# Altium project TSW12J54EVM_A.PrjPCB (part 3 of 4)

## Sheet TSW12J54EVM_A_5_Power.SchDoc
size 431 x 279 mm; Date: Not shown in title block; ApprovedBy: Not shown in title block; CheckedBy: Not shown in title block; Author: Not shown in title block; CompanyName: Not shown in title block; Engineer: Not shown in title block; Organization: Not shown in title block; Address1: Not shown in title block; Address2: Not shown in title block; Address3: Not shown in title block; Address4: Not shown in title block; DocumentNumber: 5; Revision: Use project parameter SCH_Rev; SheetNumber: 5; SheetTotal: 8; PageSetup: Record=PageOptions¦CenterHorizontal=True¦CenterVertical=True¦PrintScale=0.64¦XCorrection=1.00¦YCorrection=1.00¦PrintKind=0¦BorderSize=5000000¦LeftOffset=0¦BottomOffset=0¦Orientation=2¦PaperLength=1000¦PaperWidth=1000¦Scale=100¦PaperSource=15¦PrintQuality=600¦MediaType=1¦DitherType=10¦PaperKind=11x17¦PrintScaleMode=1
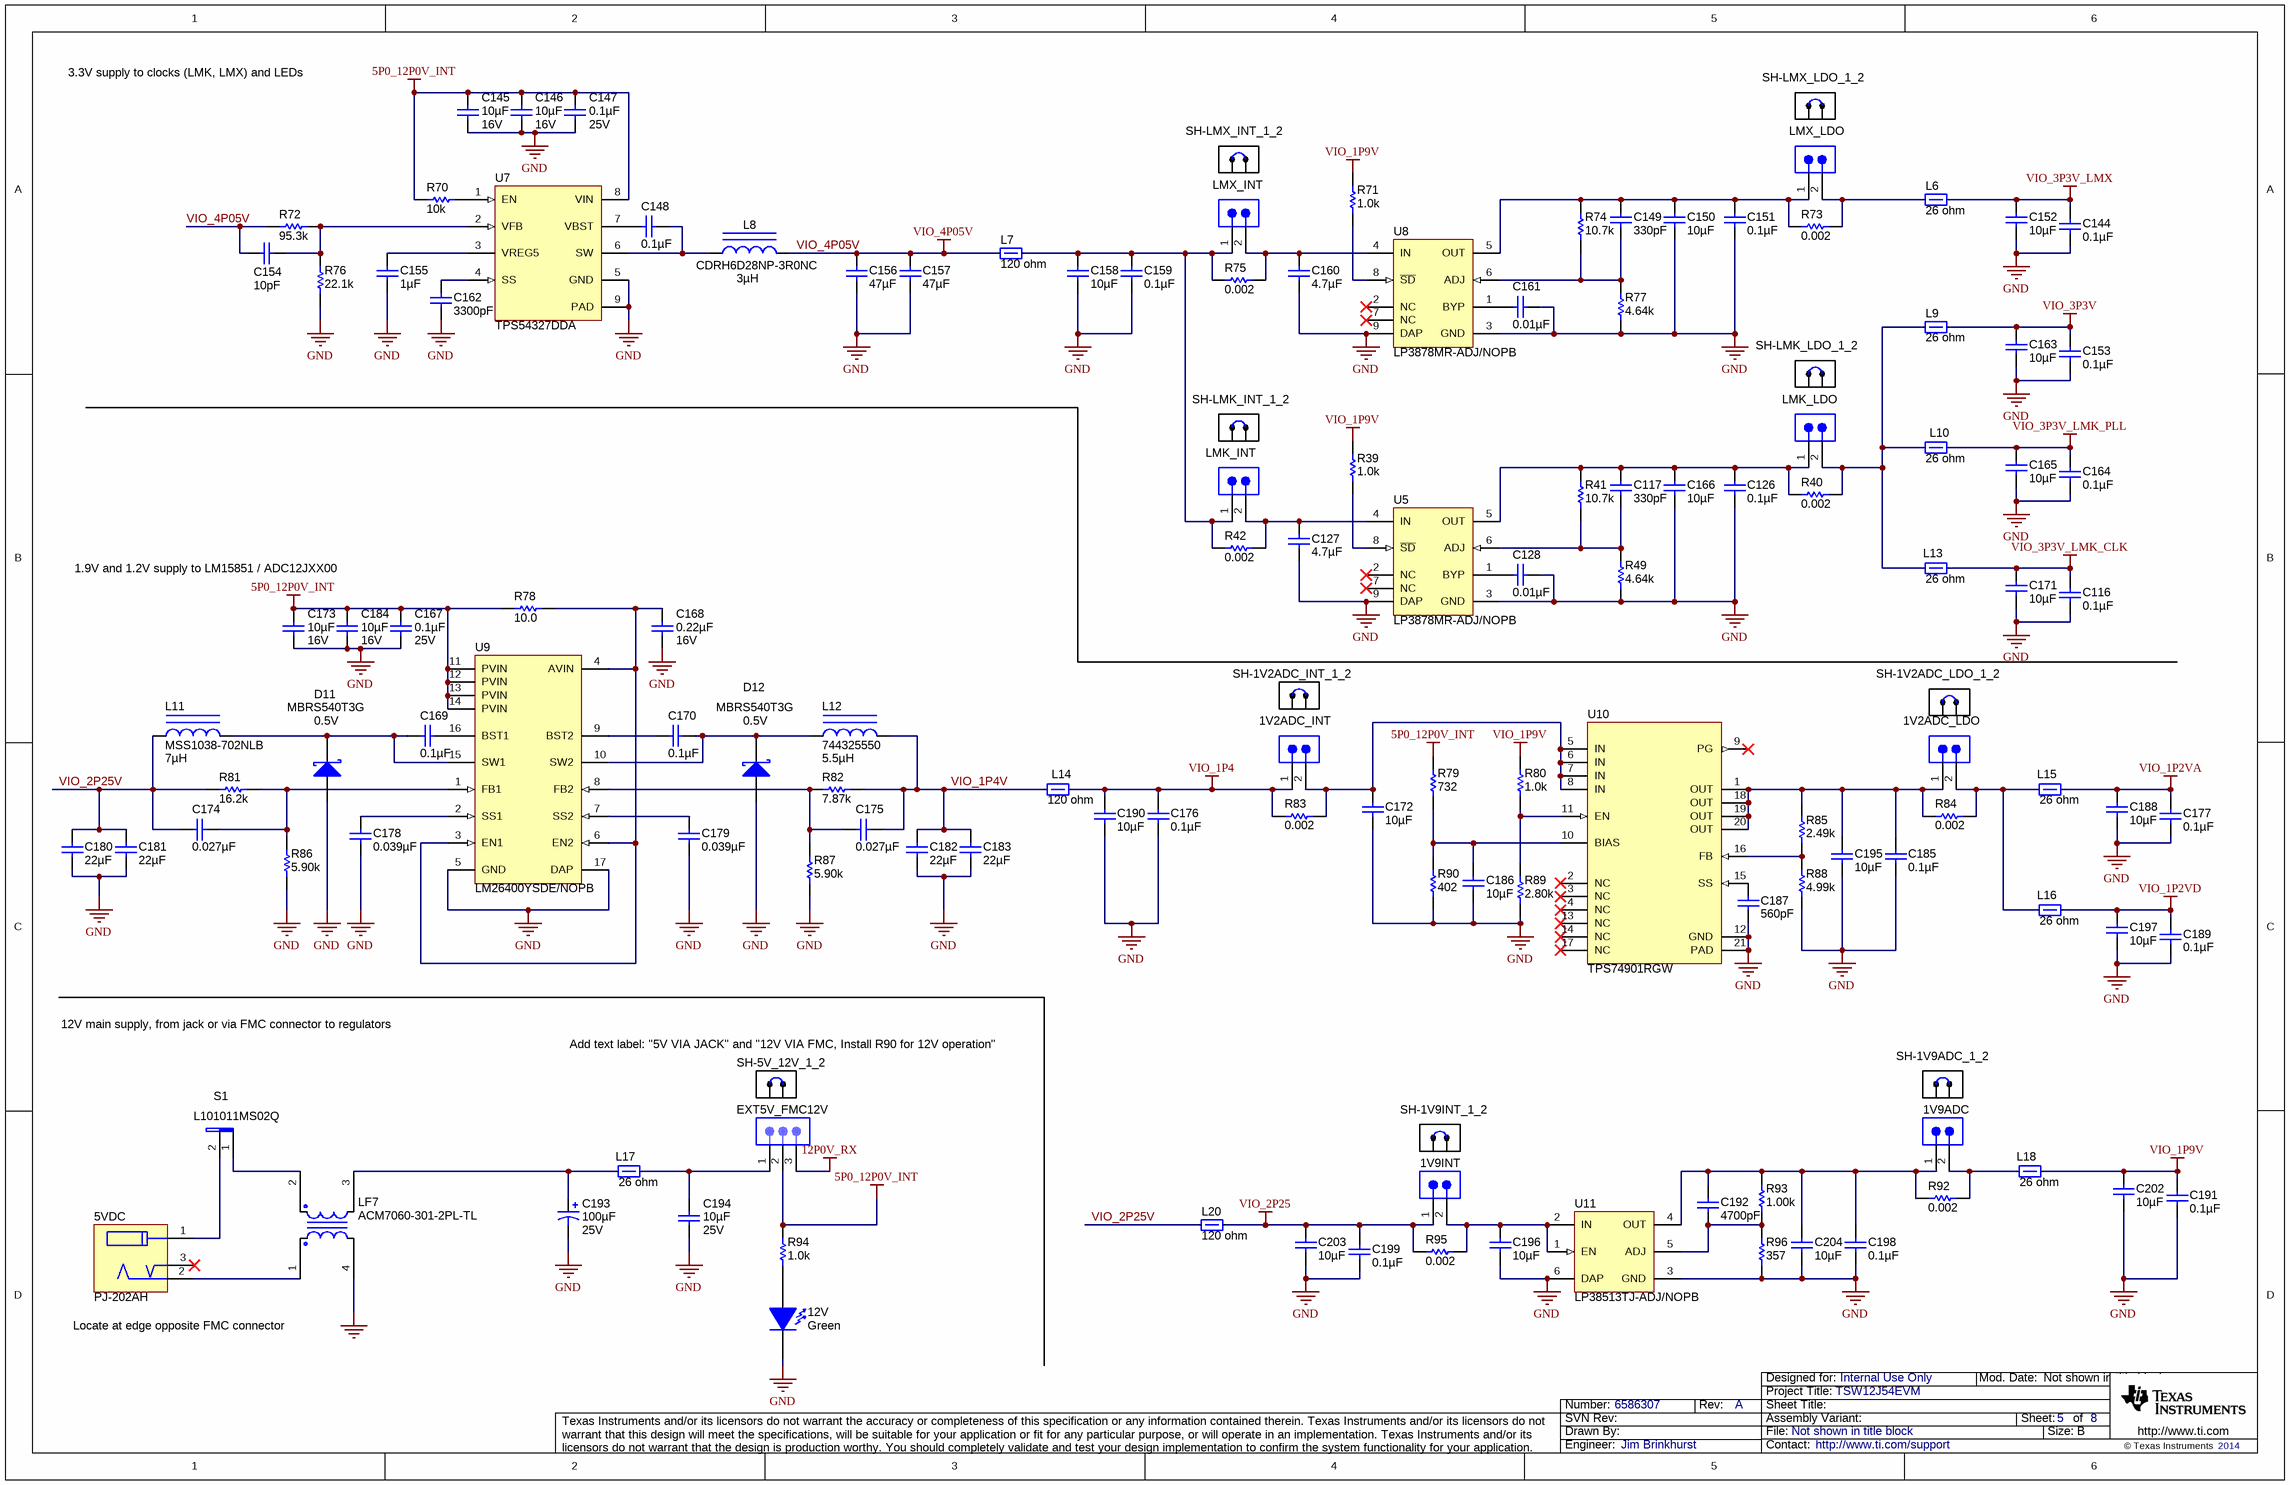
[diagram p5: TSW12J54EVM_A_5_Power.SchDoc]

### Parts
1V2ADC_INT  TSW-102-07-G-S  [TSW-102-07-G-S]  (value not drawn)
1V2ADC_LDO  TSW-102-07-G-S  [TSW-102-07-G-S]  (value not drawn)
1V9ADC  TSW-102-07-G-S  [TSW-102-07-G-S]  (value not drawn)
1V9INT  TSW-102-07-G-S  [TSW-102-07-G-S]  (value not drawn)
5VDC  PJ-202AH  [CONN_CUI-PJ-202AH]
12V  value Green  [LED_LTST-C190]  (hidden comment: LTST-C190GKT)
C116  ValueDisplayed: 0.1µF  [0603L]  (hidden comment: 06033C104JAT2A)
C117  ValueDisplayed: 330pF  [0603L]  (hidden comment: 06035A331JAT2A)
C126  ValueDisplayed: 0.1µF  [0603L]  (hidden comment: 06033C104JAT2A)
C127  ValueDisplayed: 4.7µF  [0603L]  (hidden comment: C0603C475K8PACTU)
C128  ValueDisplayed: 0.01µF  [0603L]  (hidden comment: 06031C103MAT2A)
C144  ValueDisplayed: 0.1µF  [0603L]  (hidden comment: 06033C104JAT2A)
C145  ValueDisplayed: 10µF  Value2: 16V  [0805L]  (hidden comment: EMK212BJ106KG-T)
C146  ValueDisplayed: 10µF  Value2: 16V  [0805L]  (hidden comment: EMK212BJ106KG-T)
C147  ValueDisplayed: 0.1µF  Value2: 25V  [0603L]  (hidden comment: 06033C104JAT2A)
C148  ValueDisplayed: 0.1µF  [0603L]  (hidden comment: 06033C104JAT2A)
C149  ValueDisplayed: 330pF  [0603L]  (hidden comment: 06035A331JAT2A)
C150  ValueDisplayed: 10µF  [0603L]  (hidden comment: C1608X5R1A106M)
C151  ValueDisplayed: 0.1µF  [0603L]  (hidden comment: 06033C104JAT2A)
C152  ValueDisplayed: 10µF  [0603L]  (hidden comment: C1608X5R1A106M)
C153  ValueDisplayed: 0.1µF  [0603L]  (hidden comment: 06033C104JAT2A)
C154  ValueDisplayed: 10pF  [0603L]  (hidden comment: 06035A100JAT2A)
C155  ValueDisplayed: 1µF  [0603L]  (hidden comment: C1608X5R1C105K)
C156  ValueDisplayed: 47µF  [1206L]  (hidden comment: GRM31CR60J476ME19L)
C157  ValueDisplayed: 47µF  [1206L]  (hidden comment: GRM31CR60J476ME19L)
C158  ValueDisplayed: 10µF  [0603L]  (hidden comment: C1608X5R1A106M)
C159  ValueDisplayed: 0.1µF  [0603L]  (hidden comment: 06033C104JAT2A)
C160  ValueDisplayed: 4.7µF  [0603L]  (hidden comment: C0603C475K8PACTU)
C161  ValueDisplayed: 0.01µF  [0603L]  (hidden comment: 06031C103MAT2A)
C162  ValueDisplayed: 3300pF  [0603L]  (hidden comment: GRM188R71E332KA01D)
C163  ValueDisplayed: 10µF  [0603L]  (hidden comment: C1608X5R1A106M)
C164  ValueDisplayed: 0.1µF  [0603L]  (hidden comment: 06033C104JAT2A)
C165  ValueDisplayed: 10µF  [0603L]  (hidden comment: C1608X5R1A106M)
C166  ValueDisplayed: 10µF  [0603L]  (hidden comment: C1608X5R1A106M)
C167  ValueDisplayed: 0.1µF  Value2: 25V  [0603L]  (hidden comment: 06033C104JAT2A)
C168  ValueDisplayed: 0.22µF  Value2: 16V  [0603L]  (hidden comment: C1608X7R1C224K)
C169  ValueDisplayed: 0.1µF  [0402L]  (hidden comment: GRM155R60J104KA01D)
C170  ValueDisplayed: 0.1µF  [0402L]  (hidden comment: GRM155R60J104KA01D)
C171  ValueDisplayed: 10µF  [0603L]  (hidden comment: C1608X5R1A106M)
C172  ValueDisplayed: 10µF  [0603L]  (hidden comment: C1608X5R1A106M)
C173  ValueDisplayed: 10µF  Value2: 16V  [0805L]  (hidden comment: EMK212BJ106KG-T)
C174  ValueDisplayed: 0.027µF  [0603L]  (hidden comment: GRM188R71C273KA01D)
C175  ValueDisplayed: 0.027µF  [0603L]  (hidden comment: GRM188R71C273KA01D)
C176  ValueDisplayed: 0.1µF  [0603L]  (hidden comment: 06033C104JAT2A)
C177  ValueDisplayed: 0.1µF  [0603L]  (hidden comment: 06033C104JAT2A)
C178  ValueDisplayed: 0.039µF  [0603L]  (hidden comment: 06033C393KAT2A)
C179  ValueDisplayed: 0.039µF  [0603L]  (hidden comment: 06033C393KAT2A)
C180  ValueDisplayed: 22µF  [1206L]  (hidden comment: GRM31CR61A226ME19L)
C181  ValueDisplayed: 22µF  [1206L]  (hidden comment: GRM31CR61A226ME19L)
C182  ValueDisplayed: 22µF  [1206L]  (hidden comment: GRM31CR61A226ME19L)
C183  ValueDisplayed: 22µF  [1206L]  (hidden comment: GRM31CR61A226ME19L)
C184  ValueDisplayed: 10µF  Value2: 16V  [0805L]  (hidden comment: EMK212BJ106KG-T)
C185  ValueDisplayed: 0.1µF  [0603L]  (hidden comment: 06033C104JAT2A)
C186  ValueDisplayed: 10µF  [0603L]  (hidden comment: C1608X5R1A106M)
C187  ValueDisplayed: 560pF  [0603L]  (hidden comment: 06035A561JAT2A)
C188  ValueDisplayed: 10µF  [0603L]  (hidden comment: C1608X5R1A106M)
C189  ValueDisplayed: 0.1µF  [0603L]  (hidden comment: 06033C104JAT2A)
C190  ValueDisplayed: 10µF  [0603L]  (hidden comment: C1608X5R1A106M)
C191  ValueDisplayed: 0.1µF  [0603L]  (hidden comment: 06033C104JAT2A)
C192  ValueDisplayed: 4700pF  [0603L]  (hidden comment: GRM188R71C472KA01D)
C193  ValueDisplayed: 100µF  Value2: 25V  [CAPPR250W50D630H1120]  (hidden comment: EEU-EB1E101S)
C194  ValueDisplayed: 10µF  Value2: 25V  [1210L]  (hidden comment: GRM32DC81E106KA12L)
C195  ValueDisplayed: 10µF  [0603L]  (hidden comment: C1608X5R1A106M)
C196  ValueDisplayed: 10µF  [0603L]  (hidden comment: C1608X5R1A106M)
C197  ValueDisplayed: 10µF  [0603L]  (hidden comment: C1608X5R1A106M)
C198  ValueDisplayed: 0.1µF  [0603L]  (hidden comment: 06033C104JAT2A)
C199  ValueDisplayed: 0.1µF  [0603L]  (hidden comment: 06033C104JAT2A)
C202  ValueDisplayed: 10µF  [0603L]  (hidden comment: C1608X5R1A106M)
C203  ValueDisplayed: 10µF  [0603L]  (hidden comment: C1608X5R1A106M)
C204  ValueDisplayed: 10µF  [0603L]  (hidden comment: C1608X5R1A106M)
D11  MBRS540T3G  value 0.5V  [SMC]
D12  MBRS540T3G  value 0.5V  [SMC]
EXT5V_FMC12V  PBC03SAAN  [PBC03SAAN]  (value not drawn)
L6  value 26 ohm  [0603]  (hidden comment: BLM18SG260TN1D)
L7  value 120 ohm  [0603]  (hidden comment: BLM18SG121TN1D)
L8  CDRH6D28NP-3R0NC  ValueDisplayed: 3µH  [CDRH6D28]
L9  value 26 ohm  [0603]  (hidden comment: BLM18SG260TN1D)
L10  value 26 ohm  [0603]  (hidden comment: BLM18SG260TN1D)
L11  MSS1038-702NLB  ValueDisplayed: 7µH  [MSS1038]
L12  744325550  ValueDisplayed: 5.5µH  [WE-HC6]
L13  value 26 ohm  [0603]  (hidden comment: BLM18SG260TN1D)
L14  value 120 ohm  [0603]  (hidden comment: BLM18SG121TN1D)
L15  value 26 ohm  [0603]  (hidden comment: BLM18SG260TN1D)
L16  value 26 ohm  [0603]  (hidden comment: BLM18SG260TN1D)
L17  value 26 ohm  [0603]  (hidden comment: BLM18SG260TN1D)
L18  value 26 ohm  [0603]  (hidden comment: BLM18SG260TN1D)
L20  value 120 ohm  [0603]  (hidden comment: BLM18SG121TN1D)
LF7  ACM7060-301-2PL-TL  [IND_TDK_ACM7060]
LMK_INT  TSW-102-07-G-S  [TSW-102-07-G-S]  (value not drawn)
LMK_LDO  TSW-102-07-G-S  [TSW-102-07-G-S]  (value not drawn)
LMX_INT  TSW-102-07-G-S  [TSW-102-07-G-S]  (value not drawn)
LMX_LDO  TSW-102-07-G-S  [TSW-102-07-G-S]  (value not drawn)
R39  value 1.0k  [0603L]  (hidden comment: RC0603JR-071KL)
R40  value 0.002  [1206]  (hidden comment: CSNL1206FT2L00)
R41  value 10.7k  [0603L]  (hidden comment: CRCW060310K7FKEA)
R42  value 0.002  [1206]  (hidden comment: CSNL1206FT2L00)
R49  value 4.64k  [0603L]  (hidden comment: RC0603FR-074K64L)
R70  value 10k  [0603L]  (hidden comment: RC0603JR-0710KL)
R71  value 1.0k  [0603L]  (hidden comment: RC0603JR-071KL)
R72  ValueDisplayed: 95.3k  [0603L]  (hidden comment: RC0603FR-0795K3L)
R73  value 0.002  [1206]  (hidden comment: CSNL1206FT2L00)
R74  value 10.7k  [0603L]  (hidden comment: CRCW060310K7FKEA)
R75  value 0.002  [1206]  (hidden comment: CSNL1206FT2L00)
R76  value 22.1k  [0603L]  (hidden comment: CRCW060322K1FKEA)
R77  value 4.64k  [0603L]  (hidden comment: RC0603FR-074K64L)
R78  value 10.0  [0603L]  (hidden comment: RC0603FR-0710RL)
R79  value 732  [0603L]  (hidden comment: CRCW0603732RFKEA)
R80  value 1.0k  [0603L]  (hidden comment: RC0603JR-071KL)
R81  value 16.2k  [0603L]  (hidden comment: CRCW060316K2FKEA)
R82  value 7.87k  [0603L]  (hidden comment: CRCW06037K87FKEA)
R83  value 0.002  [1206]  (hidden comment: CSNL1206FT2L00)
R84  value 0.002  [1206]  (hidden comment: CSNL1206FT2L00)
R85  value 2.49k  [0603L]  (hidden comment: CRCW06032K49FKEA)
R86  value 5.90k  [0603L]  (hidden comment: CRCW06035K90FKEA)
R87  value 5.90k  [0603L]  (hidden comment: CRCW06035K90FKEA)
R88  value 4.99k  [0603L]  (hidden comment: CRCW06034K99FKEA)
R89  value 2.80k  [0603L]  (hidden comment: CRCW06032K80FKEA)
R90  value 402  [0603L]  (hidden comment: RC0603FR-07402RL)
R92  value 0.002  [1206]  (hidden comment: CSNL1206FT2L00)
R93  value 1.00k  [0603L]  (hidden comment: RC0603FR-071KL)
R94  value 1.0k  [1206L]  (hidden comment: CRCW12061K00JNEA)
R95  value 0.002  [1206]  (hidden comment: CSNL1206FT2L00)
R96  value 357  [0603L]  (hidden comment: RC0603FR-07357RL)
S1  L101011MS02Q  [SW_ L101011MS02Q]
SH-1V2ADC_INT_1_2  SNT-100-BK-G  [SNT-100-BK-G]  (value not drawn)
SH-1V2ADC_LDO_1_2  SNT-100-BK-G  [SNT-100-BK-G]  (value not drawn)
SH-1V9ADC_1_2  SNT-100-BK-G  [SNT-100-BK-G]  (value not drawn)
SH-1V9INT_1_2  SNT-100-BK-G  [SNT-100-BK-G]  (value not drawn)
SH-5V_12V_1_2  SNT-100-BK-G  [SNT-100-BK-G]  (value not drawn)
SH-LMK_INT_1_2  SNT-100-BK-G  [SNT-100-BK-G]  (value not drawn)
SH-LMK_LDO_1_2  SNT-100-BK-G  [SNT-100-BK-G]  (value not drawn)
SH-LMX_INT_1_2  SNT-100-BK-G  [SNT-100-BK-G]  (value not drawn)
SH-LMX_LDO_1_2  SNT-100-BK-G  [SNT-100-BK-G]  (value not drawn)
U5  LP3878MR-ADJ/NOPB  [MRA08A_N]
U7  TPS54327DDA  [DDA0008B_L]
U8  LP3878MR-ADJ/NOPB  [MRA08A_N]
U9  LM26400YSDE/NOPB  [SDA16A]
U10  TPS74901RGW  [RGW0020A]
U11  LP38513TJ-ADJ/NOPB  [TJ5A_N]

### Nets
5P0_12P0V_INT: C145.1 C146.1 C147.1 C167.1 C173.1 C184.1 EXT5V_FMC12V.2 R70.1 R78.1 R79.2 R94.2 U7.8(VIN) U9.11(PVIN) U9.12(PVIN) U9.13(PVIN) U9.14(PVIN)
12P0V_RX: EXT5V_FMC12V.3
GND: 12V.2(K) C116.2 C126.2 C127.2 C128.2 C144.2 C145.2 C146.2 C147.2 C150.2 C151.2 C152.2 C153.2 C155.2 C156.1 C157.1 C158.2 C159.2 C160.2 C161.2 C162.2 C163.2 C164.2 C165.2 C166.2 C167.2 C168.2 C171.2 C172.2 C173.2 C176.2 C177.2 C178.2 C179.2 C180.2 C181.2 C182.2 C183.2 C184.2 C185.2 C186.2 C187.2 C188.2 C189.2 C190.2 C191.2 C193.2(-) C194.2 C195.2 C196.2 C197.2 C198.2 C199.2 C202.2 C203.2 C204.2 D11.2(A) D12.2(A) LF7.4 R49.1 R76.1 R77.1 R86.1 R87.1 R88.1 R89.1 R90.1 R96.1 U5.3(GND) U5.9(DAP) U7.5(GND) U7.9(PAD) U8.3(GND) U8.9(DAP) U9.5(GND) U9.17(DAP) U10.12(GND) U10.21(PAD) U11.3(GND) U11.6(DAP)
VIO_1P2VA: C177.1 C188.1 L15.2
VIO_1P2VD: C189.1 C197.1 L16.2
VIO_1P4: 1V2ADC_INT.1 C176.1 C190.1 L14.2 R83.1
VIO_1P9V: C191.1 C202.1 L18.2 R39.1 R71.1 R80.1
VIO_2P25: 1V9INT.1 C199.1 C203.1 L20.2 R95.1
VIO_3P3V: C153.1 C163.1 L9.2
VIO_3P3V_LMK_CLK: C116.1 C171.1 L13.2
VIO_3P3V_LMK_PLL: C164.1 C165.1 L10.2
VIO_3P3V_LMX: C144.1 C152.1 L6.2
VIO_4P05V: C154.2 C156.2 C157.2 L7.1 L8.2 R72.1
VIO_1P4V: C175.1 C182.1 C183.1 L12.2 L14.1 R82.2
VIO_2P25V: C174.2 C180.1 C181.1 L11.1 L20.1 R81.1
Net1V2ADC_INT_2: 1V2ADC_INT.2 C172.1 R83.2 U10.5(IN) U10.6(IN) U10.7(IN) U10.8(IN)
Net1V2ADC_LDO_1: 1V2ADC_LDO.1 C185.1 C195.1 R84.1 R85.2 U10.1(OUT) U10.18(OUT) U10.19(OUT) U10.20(OUT)
Net1V2ADC_LDO_2: 1V2ADC_LDO.2 L15.1 L16.1 R84.2
Net1V9ADC_1: 1V9ADC.1 C192.1 C198.1 C204.1 R92.1 R93.2 U11.4(OUT)
Net1V9ADC_2: 1V9ADC.2 L18.1 R92.2
Net1V9INT_2: 1V9INT.2 C196.1 R95.2 U11.1(EN) U11.2(IN)
Net5VDC_1: 5VDC.1 S1.2
Net5VDC_2: 5VDC.2 LF7.1
Net12V_1: 12V.1(A) R94.1
NetC117_1: C117.1 C126.1 C166.1 LMK_LDO.1 R40.1 R41.2 U5.5(OUT)
NetC117_2: C117.2 R41.1 R49.2 U5.6(ADJ)
NetC127_1: C127.1 LMK_INT.2 R42.2 U5.4(IN)
NetC128_1: C128.1 U5.1(BYP)
NetC148_1: C148.1 L8.1 U7.6(SW)
NetC148_2: C148.2 U7.7(VBST)
NetC149_1: C149.1 C150.1 C151.1 LMX_LDO.1 R73.1 R74.2 U8.5(OUT)
NetC149_2: C149.2 R74.1 R77.2 U8.6(ADJ)
NetC154_1: C154.1 R72.2 R76.2 U7.2(VFB)
NetC155_1: C155.1 U7.3(VREG5)
NetC158_1: C158.1 C159.1 L7.2 LMK_INT.1 LMX_INT.1 R42.1 R75.1
NetC160_1: C160.1 LMX_INT.2 R75.2 U8.4(IN)
NetC161_1: C161.1 U8.1(BYP)
NetC162_1: C162.1 U7.4(SS)
NetC168_1: C168.1 R78.2 U9.3(EN1) U9.4(AVIN) U9.6(EN2)
NetC169_1: C169.1 U9.16(BST1)
NetC169_2: C169.2 D11.1(K) L11.2 U9.15(SW1)
NetC170_1: C170.1 D12.1(K) L12.1 U9.10(SW2)
NetC170_2: C170.2 U9.9(BST2)
NetC174_1: C174.1 R81.2 R86.2 U9.1(FB1)
NetC175_2: C175.2 R82.1 R87.2 U9.8(FB2)
NetC178_1: C178.1 U9.2(SS1)
NetC179_1: C179.1 U9.7(SS2)
NetC186_1: C186.1 R79.1 R90.2 U10.10(BIAS)
NetC187_1: C187.1 U10.15(SS)
NetC192_2: C192.2 R93.1 R96.2 U11.5(ADJ)
NetC193_1: C193.1(+) L17.1 LF7.3
NetC194_1: C194.1 EXT5V_FMC12V.1 L17.2
NetL6_1: L6.1 LMX_LDO.2 R73.2
NetL9_1: L9.1 L10.1 L13.1 LMK_LDO.2 R40.2
NetLF7_2: LF7.2 S1.1
NetR39_2: R39.2 U5.8(~{SD})
NetR70_2: R70.2 U7.1(EN)
NetR71_2: R71.2 U8.8(~{SD})
NetR80_2: R80.2 R89.2 U10.11(EN)
NetR85_1: R85.1 R88.2 U10.16(FB)

Not connected (* = marked no-connect by the designer): 5VDC 3*; U5 2(NC)* 7(NC)*; U8 2(NC)* 7(NC)*; U10 2(NC)* 3(NC)* 4(NC)* 9(PG)* 13(NC)* 14(NC)* 17(NC)*

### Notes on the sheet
- 3.3V supply to clocks (LMK, LMX) and LEDs
- 1.9V and 1.2V supply to LM15851 / ADC12JXX00
- 12V main supply, from jack or via FMC connector to regulators
- (near SH-5V_12V_1_2) Add text label: "5V VIA JACK" and "12V VIA FMC, Install R90 for 12V operation"
- (near 5VDC) Locate at edge opposite FMC connector

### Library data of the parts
1V2ADC_INT 1V2ADC_LDO 1V9ADC 1V9INT LMK_INT LMK_LDO LMX_INT LMX_LDO = TSW-102-07-G-S: Header, TH, 100mil, 2x1, Gold plated, 230 mil above insulator; Manufacturer: Samtec, Inc.; U/M: EA
5VDC = PJ-202AH: Connector, DC Jack 2.1X5.5 mm, TH; Manufacturer: CUI Inc.; SymbolCreator: a0799628; U/M: EA
12V = LTST-C190GKT: LED, Green, SMD; Manufacturer: Lite-On; Vf_V: 2.1; Value2: 2.1V; Io_A: 0.02; Power_TotalModule: 0.1; Value1: 0.1W; U/M: EA
C116 C126 C144 C147 C148 C151 C153 C159 C164 C167 C176 C177 C185 C189 C191 C198 C199 = 06033C104JAT2A: CAP, CERM, 0.1uF, 25V, +/-5%, X7R, 0603; Manufacturer: AVX; Polarized: N; CompType: Capacitor; U/M: EA; Cap_F: 0.0000001; Tolerance_%: 5; ESR_Ohm: 0.05; Value1: 0.05 ohm; VDC_V: 25; TaMin_C: -55; TaMax_C: 125; Cap_Case: 0603
C117 C149 = 06035A331JAT2A: CAP, CERM, 330pF, 50V, +/-5%, C0G/NP0, 0603; Manufacturer: AVX; Polarized: N; CompType: Capacitor; U/M: EA; Cap_F: 0.00000000033; Tolerance_%: 5; ESR_Ohm: 0.071; Value1: 0.071 ohm; VDC_V: 50; TaMin_C: -55; TaMax_C: 125; Cap_Case: 0603
C127 C160 = C0603C475K8PACTU: CAP, CERM, 4.7uF, 10V, +/-10%, X5R, 0603; Manufacturer: Kemet; Polarized: N; CompType: Capacitor; U/M: EA; Cap_F: 0.0000047; Tolerance_%: 10; ESR_Ohm: 0.006; Value1: 0.006 ohm; IRMS_A: 7.24; TaMin_C: -55; TaMax_C: 85; Cap_Case: 0603
C128 C161 = 06031C103MAT2A: CAP, CERM, 0.01uF, 100V, +/-20%, X7R, 0603; Manufacturer: AVX; Polarized: N; CompType: Capacitor; U/M: EA; Cap_F: 0.00000001; Tolerance_%: 20; ESR_Ohm: 0.098; Value1: 0.098 ohm; VDC_V: 100; TaMin_C: -55; TaMax_C: 125; Cap_Case: 0603
C145 C146 C173 C184 = EMK212BJ106KG-T: CAP, CERM, 10uF, 16V, +/-10%, X5R, 0805; Manufacturer: Taiyo Yuden; Polarized: N; CompType: Capacitor; U/M: EA; Cap_F: 0.00001; Tolerance_%: 10; Value1: Unknown; VDC_V: 16; TaMin_C: -55; TaMax_C: 85; Cap_Case: 0805
C150 C152 C158 C163 C165 C166 C171 C172 C186 C188 C190 C195-C197 C202-C204 = C1608X5R1A106M: CAP, CERM, 10uF, 10V, +/-10%, C0G/NP0, 0603; Manufacturer: TDK; Polarized: N; CompType: Capacitor; U/M: EA; Cap_F: 0.00001; Tolerance_%: 10; ESR_Ohm: 0.0078; Value1: 0.0078 ohm; IRMS_A: 1.85; TaMin_C: -55; TaMax_C: 85; Cap_Case: 0603
C154 = 06035A100JAT2A: CAP, CERM, 10pF, 50V, +/-5%, C0G/NP0, 0603; Manufacturer: AVX; Polarized: N; CompType: Capacitor; U/M: EA; Cap_F: 0.00000000001; Tolerance_%: 5; ESR_Ohm: 0.403; Value1: 0.403 ohm; VDC_V: 50; TaMin_C: -55; TaMax_C: 125; Cap_Case: 0603
C155 = C1608X5R1C105K: CAP, CERM, 1uF, 16V, +/-10%, X5R, 0603; Manufacturer: TDK; Polarized: N; CompType: Capacitor; U/M: EA; Cap_F: 0.000001; Tolerance_%: 10; ESR_Ohm: 0.0057; Value1: 0.0057 ohm; VDC_V: 16; TaMin_C: -55; TaMax_C: 85; Cap_Case: 0603
C156 C157 = GRM31CR60J476ME19L: CAP, CERM, 47uF, 6.3V, +/-20%, X5R, 1206; Manufacturer: MuRata; Polarized: N; CompType: Capacitor; U/M: EA; Cap_F: 0.000047; Tolerance_%: 20; ESR_Ohm: 0.003; Value1: 0.003 ohm; VDC_V: 6.3; TaMin_C: -55; TaMax_C: 85; Cap_Case: 1206
C162 = GRM188R71E332KA01D: CAP, CERM, 3300pF, 25V, +/-10%, X7R, 0603; Manufacturer: MuRata; Polarized: N; CompType: Capacitor; U/M: EA; Cap_F: 0.0000000033; Tolerance_%: 10; VDC_V: 25; TaMin_C: -55; TaMax_C: 125; Cap_Case: 0603
C168 = C1608X7R1C224K: CAP, CERM, 0.22uF, 16V, +/-10%, X7R, 0603; Manufacturer: TDK; Polarized: N; CompType: Capacitor; U/M: EA; Cap_F: 0.00000022; Tolerance_%: 10; ESR_Ohm: 0.0125; Value1: 0.0125 ohm; VDC_V: 16; TaMin_C: -55; TaMax_C: 125; Cap_Case: 0603
C169 C170 = GRM155R60J104KA01D: CAP, CERM, 0.1uF, 6.3V, +/-10%, X5R, 0402; Manufacturer: MuRata; Polarized: N; CompType: Capacitor; U/M: EA; Cap_F: 0.0000001; Tolerance_%: 10; VDC_V: 6.3; TaMin_C: -55; TaMax_C: 85; Cap_Case: 0402
C174 C175 = GRM188R71C273KA01D: CAP, CERM, 0.027uF, 16V, +/-10%, X7R, 0603; Manufacturer: MuRata; Polarized: N; CompType: Capacitor; U/M: EA; Cap_F: 0.000000027; Tolerance_%: 10; VDC_V: 16; TaMin_C: -55; TaMax_C: 125; Cap_Case: 0603
C178 C179 = 06033C393KAT2A: CAP, CERM, 0.039uF, 25V, +/-10%, X7R, 0603; Manufacturer: AVX; Polarized: N; CompType: Capacitor; U/M: EA; Cap_F: 0.000000039; Tolerance_%: 10; ESR_Ohm: 0.056; Value1: 0.056 ohm; VDC_V: 25; TaMin_C: -55; TaMax_C: 125; Cap_Case: 0603
C180-C183 = GRM31CR61A226ME19L: CAP, CERM, 22uF, 10V, +/-20%, X5R, 1206; Manufacturer: MuRata; Polarized: N; CompType: Capacitor; U/M: EA; Cap_F: 0.000022; Tolerance_%: 20; ESR_Ohm: 0.007; Value1: 0.007 ohm; VDC_V: 10; TaMin_C: -55; TaMax_C: 85; Cap_Case: 1206
C187 = 06035A561JAT2A: CAP, CERM, 560pF, 50V, +/-5%, C0G/NP0, 0603; Manufacturer: AVX; Polarized: N; CompType: Capacitor; U/M: EA; Cap_F: 0.00000000056; Tolerance_%: 5; ESR_Ohm: 0.059; Value1: 0.059 ohm; VDC_V: 50; TaMin_C: -55; TaMax_C: 125; Cap_Case: 0603
C192 = GRM188R71C472KA01D: CAP, CERM, 4700pF, 16V, +/-10%, X7R, 0603; Manufacturer: MuRata; Polarized: N; CompType: Capacitor; U/M: EA; Cap_F: 0.0000000047; Tolerance_%: 10; VDC_V: 16; TaMin_C: -55; TaMax_C: 125; Cap_Case: 0603
C193 = EEU-EB1E101S: CAP, AL, 100uF, 25V, +/-20%, TH; Manufacturer: Panasonic; Polarized: Y; CompType: Capacitor; U/M: EA; Cap_F: 0.0001; Tolerance_%: 20; Value1: Unknown; VDC_V: 25; IRMS_A: 0.095; TaMin_C: -40; TaMax_C: 105; Cap_Case: Radial 6.3x11.2
C194 = GRM32DC81E106KA12L: CAP, CERM, 10uF, 25V, +/-10%, X6S, 1210; Manufacturer: MuRata; Polarized: N; CompType: Capacitor; U/M: EA; Cap_F: 0.00001; Tolerance_%: 10; VDC_V: 25; TaMin_C: -55; TaMax_C: 105; Cap_Case: 1210
D11 D12 = MBRS540T3G: Diode, Schottky, 40V, 5A, SMC; Manufacturer: ON Semiconductor; U/M: EA; Vf_V: 0.5; Io_A: 5; Vr_V: 40; TJmax_C: 150; RJC_CperW: 12
EXT5V_FMC12V = PBC03SAAN: Header, TH, 100mil, 1x3, Gold plated, 230 mil above insulator; Manufacturer: Sullins Connector Solutions; U/M: EA
L6 L9 L10 L13 L15-L18 = BLM18SG260TN1D: 6A Ferrite Bead, 26 ohm @ 100MHz, SMD; Manufacturer: MuRata; Imax_A: 6; DCR_ohm: 0.007; Value1: 0.007 ohm; ZTyp@100MHz_Ohm: 26; U/M: EA
L7 L14 L20 = BLM18SG121TN1D: 3A Ferrite Bead, 120 ohm @ 100MHz, SMD; Manufacturer: MuRata; Imax_A: 3; DCR_ohm: 0.025; Value1: 0.025 ohm; ZTyp@100MHz_Ohm: 120; U/M: EA
L8 = CDRH6D28NP-3R0NC: Inductor, Shielded Drum Core, Ferrite, 3uH, 3A, 0.024 ohm, SMD; Manufacturer: Sumida; Ind_H: 3.0E-6; Imax_A: 3; Irms: 3A @ 30C rise; Isat: 3A @ 35% inductance drop; DCR_ohm: 0.024; U/M: EA
L11 = MSS1038-702NLB: Inductor, Shielded Drum Core, Ferrite, 7uH, 4.35A, 0.03 ohm, SMD; Manufacturer: Coilcraft; Ind_H: 7.0E-6; Imax_A: 4.35; Irms: 4.35A @ 40C rise; Isat: 5.6A @ 30% inductance drop; DCR_ohm: 0.03; U/M: EA
L12 = 744325550: Inductor, Shielded Drum Core, Superflux, 5.5uH, 10A, 0.0112 ohm, SMD; Manufacturer: Wurth Elektronik eiSos; Ind_H: 5.5E-6; Imax_A: 10; Irms: 10A @ 50C rise; Isat: 12A @ 30% inductance drop; DCR_ohm: 0.0112; U/M: EA
LF7 = ACM7060-301-2PL-TL: Coupled inductor, 5A, 0.01 ohm, SMD; Manufacturer: TDK; SymbolCreator: a0799628; Config: Common Chokes; Value: uH; DCR_Ohm: 0.01; Isat: 5; U/M: EA
R39 R71 R80 = RC0603JR-071KL: RES, 1.0k ohm, 5%, 0.1W, 0603; Manufacturer: Yageo America; CompType: Resistor; Res_ohm: 1000; Value_Code: 1k00; Tolerance_%: 5; Power_W: 0.1; VDC_V: 50; TempCo: 100 ppm/C; EIA_Code: E24; U/M: EA
R40 R42 R73 R75 R83 R84 R92 R95 = CSNL1206FT2L00: RES, 0.002 ohm, 1%, 1W, 1206; Manufacturer: Stackpole Electronics Inc; CompType: Resistor; Value_Code: R002; Tolerance_%: 1; TempCo: 50 ppm/C; U/M: EA
R41 R74 = CRCW060310K7FKEA: RES, 10.7k ohm, 1%, 0.1W, 0603; Manufacturer: Vishay-Dale; CompType: Resistor; Res_ohm: 10700; Value_Code: 10k7; Tolerance_%: 1; Power_W: 0.1; VDC_V: 75; TempCo: 100 ppm/C; EIA_Code: E96; U/M: EA
R49 R77 = RC0603FR-074K64L: RES, 4.64k ohm, 1%, 0.1W, 0603; Manufacturer: Yageo America; CompType: Resistor; Res_ohm: 4640; Value_Code: 4k64; Tolerance_%: 1; Power_W: 0.1; VDC_V: 150; TempCo: 200 ppm/C; EIA_Code: E96; U/M: EA
R70 = RC0603JR-0710KL: RES, 10k ohm, 5%, 0.1W, 0603; Manufacturer: Yageo America; CompType: Resistor; Res_ohm: 10000; Value_Code: 10k0; Tolerance_%: 5; Power_W: 0.1; VDC_V: 50; TempCo: 100 ppm/C; EIA_Code: E24; U/M: EA
R72 = RC0603FR-0795K3L: RES, 95.3 k, 1%, 0.1 W, 0603; Manufacturer: Yageo America; CompType: Resistor; Value: 95.3k; Res_ohm: 95300; Value_Code: 95k3; Tolerance_%: 1; Power_W: 0.1; Value2: 0.1W; VDC_V: 150; TempCo: 200 ppm/C; EIA_Code: E96; U/M: EA
R76 = CRCW060322K1FKEA: RES, 22.1k ohm, 1%, 0.1W, 0603; Manufacturer: Vishay-Dale; CompType: Resistor; Res_ohm: 22100; Value_Code: 22k1; Tolerance_%: 1; Power_W: 0.1; VDC_V: 75; TempCo: 100 ppm/C; EIA_Code: E96; U/M: EA
R78 = RC0603FR-0710RL: RES, 10.0 ohm, 1%, 0.1W, 0603; Manufacturer: Yageo America; CompType: Resistor; Res_ohm: 10; Value_Code: 10R0; Tolerance_%: 1; Power_W: 0.1; VDC_V: 150; TempCo: 200 ppm/C; EIA_Code: E96; U/M: EA
R79 = CRCW0603732RFKEA: RES, 732 ohm, 1%, 0.1W, 0603; Manufacturer: Vishay-Dale; CompType: Resistor; Value_Code: 732R; Tolerance_%: 1; Power_W: 0.1; VDC_V: 75; TempCo: 100 ppm/C; EIA_Code: E96; U/M: EA
R81 = CRCW060316K2FKEA: RES, 16.2k ohm, 1%, 0.1W, 0603; Manufacturer: Vishay-Dale; CompType: Resistor; Res_ohm: 16200; Value_Code: 16k2; Tolerance_%: 1; Power_W: 0.1; VDC_V: 75; TempCo: 100 ppm/C; EIA_Code: E96; U/M: EA
R82 = CRCW06037K87FKEA: RES, 7.87k ohm, 1%, 0.1W, 0603; Manufacturer: Vishay-Dale; CompType: Resistor; Res_ohm: 7870; Value_Code: 7k87; Tolerance_%: 1; Power_W: 0.1; VDC_V: 75; TempCo: 100 ppm/C; EIA_Code: E96; U/M: EA
R85 = CRCW06032K49FKEA: RES, 2.49k ohm, 1%, 0.1W, 0603; Manufacturer: Vishay-Dale; CompType: Resistor; Res_ohm: 2490; Value_Code: 2k49; Tolerance_%: 1; Power_W: 0.1; VDC_V: 75; TempCo: 100 ppm/C; EIA_Code: E96; U/M: EA
R86 R87 = CRCW06035K90FKEA: RES, 5.90k ohm, 1%, 0.1W, 0603; Manufacturer: Vishay-Dale; CompType: Resistor; Res_ohm: 5900; Value_Code: 5k90; Tolerance_%: 1; Power_W: 0.1; VDC_V: 75; TempCo: 100 ppm/C; EIA_Code: E96; U/M: EA
R88 = CRCW06034K99FKEA: RES, 4.99k ohm, 1%, 0.1W, 0603; Manufacturer: Vishay-Dale; CompType: Resistor; Res_ohm: 4990; Value_Code: 4k99; Tolerance_%: 1; Power_W: 0.1; VDC_V: 75; TempCo: 100 ppm/C; EIA_Code: E96; U/M: EA
R89 = CRCW06032K80FKEA: RES, 2.80k ohm, 1%, 0.1W, 0603; Manufacturer: Vishay-Dale; CompType: Resistor; Res_ohm: 2800; Value_Code: 2k80; Tolerance_%: 1; Power_W: 0.1; VDC_V: 75; TempCo: 100 ppm/C; EIA_Code: E96; U/M: EA
R90 = RC0603FR-07402RL: RES, 402 ohm, 1%, 0.1W, 0603; Manufacturer: Yageo America; CompType: Resistor; Value_Code: 402R; Tolerance_%: 1; Power_W: 0.1; VDC_V: 150; TempCo: 200 ppm/C; EIA_Code: E96; U/M: EA
R93 = RC0603FR-071KL: RES, 1.00k ohm, 1%, 0.1W, 0603; Manufacturer: Yageo America; CompType: Resistor; Res_ohm: 1000; Value_Code: 1k00; Tolerance_%: 1; Power_W: 0.1; VDC_V: 150; TempCo: 200 ppm/C; EIA_Code: E96; U/M: EA
R94 = CRCW12061K00JNEA: RES, 1.0k ohm, 5%, 0.25W, 1206; Manufacturer: Vishay-Dale; CompType: Resistor; Res_ohm: 1000; Value_Code: 1k00; Tolerance_%: 5; Power_W: 0.25; VDC_V: 200; TempCo: 200 ppm/C; EIA_Code: E24; U/M: EA
R96 = RC0603FR-07357RL: RES, 357 ohm, 1%, 0.1W, 0603; Manufacturer: Yageo America; CompType: Resistor; Value_Code: 357R; Tolerance_%: 1; Power_W: 0.1; VDC_V: 150; TempCo: 200 ppm/C; EIA_Code: E96; U/M: EA
S1 = L101011MS02Q: SWITCH SLIDE SPST 4A PCB, TH; Manufacturer: C&K Components; Symbol Creator: a0411947; VDC_V: 125; SwitchFunction: Off-On; PositionCount: 1; CurrentRating_mA: 4000
SH-1V2ADC_INT_1_2 SH-1V2ADC_LDO_1_2 SH-1V9ADC_1_2 SH-1V9INT_1_2 SH-5V_12V_1_2 SH-LMK_INT_1_2 SH-LMK_LDO_1_2 SH-LMX_INT_1_2 SH-LMX_LDO_1_2 = SNT-100-BK-G: Shunt, 100mil, Gold plated, Black; Manufacturer: Samtec, Inc.; Alternate Manufacturer: 3M; Alternate PartNumber: 969102-0000-DA; Value: 1x2; Note: You can "mate" this to a header by matching the designator.  i.e. use SH-J3 for header J3
U5 U8 = LP3878MR-ADJ/NOPB: Micropower 800mA Low Noise "Ceramic Stable" Adjustable Voltage Regulator for 1V to 5V Applications, 8-pin PSOP, Pb-Free; Manufacturer: National Semiconductor; PackageTopMarking: NSXYTT*3878*MRADJ; PowerWise: N; CompType: LDO IC
U7 = TPS54327DDA: 3-A OUTPUT SINGLE SYNCRONOUS STEP DOWN SWITCHER WITH INTEGRATED FET(SWIFT), DDA0008B; Alternate Manufacturer: None; Manufacturer: Texas Instruments; SymbolCreator: a0411947; CompType: IC; U/M: EA
U9 = LM26400YSDE/NOPB: Dual 2A, 500kHz Wide Input Range Buck Regulator, 16-pin LLP, Pb-Free; Manufacturer: National Semiconductor; PackageTopMarking: NS*UZXYTT*L26400Y; PowerWise: N; CompType: Switcher
U10 = TPS74901RGW: 3.0A Low Dropout Linear Regulator with Programmable Soft-Start, RGW0020A; Alternate Manufacturer: None; Manufacturer: Texas Instruments; SymbolCreator: a0411947; CompType: IC; U/M: EA
U11 = LP38513TJ-ADJ/NOPB: 3A Fast-Transient Response Adjustable Low-Dropout Linear Voltage Regulator, 5-pin TO-263 Thin, Pb-Free; Manufacturer: National Semiconductor; PackageTopMarking: NSUZXYTTE#*LP38513*TJ-ADJ; PowerWise: N; CompType: LDO IC

## Sheet TSW12J54EVM_A_6_Power.SchDoc
size 431 x 279 mm; Date: Not shown in title block; ApprovedBy: Not shown in title block; CheckedBy: Not shown in title block; Author: Not shown in title block; CompanyName: Not shown in title block; Engineer: Not shown in title block; Organization: Not shown in title block; Address1: Not shown in title block; Address2: Not shown in title block; Address3: Not shown in title block; Address4: Not shown in title block; DocumentNumber: 6; Revision: Use project parameter SCH_Rev; SheetNumber: 6; SheetTotal: 8; PageSetup: Record=PageOptions¦CenterHorizontal=True¦CenterVertical=True¦PrintScale=1.00¦XCorrection=1.00¦YCorrection=1.00¦PrintKind=0¦BorderSize=5000000¦LeftOffset=0¦BottomOffset=0¦Orientation=2¦PaperLength=1000¦PaperWidth=1000¦Scale=100¦PaperSource=15¦PrintQuality=600¦MediaType=1¦DitherType=10¦PaperKind=Letter¦PrintScaleMode=1
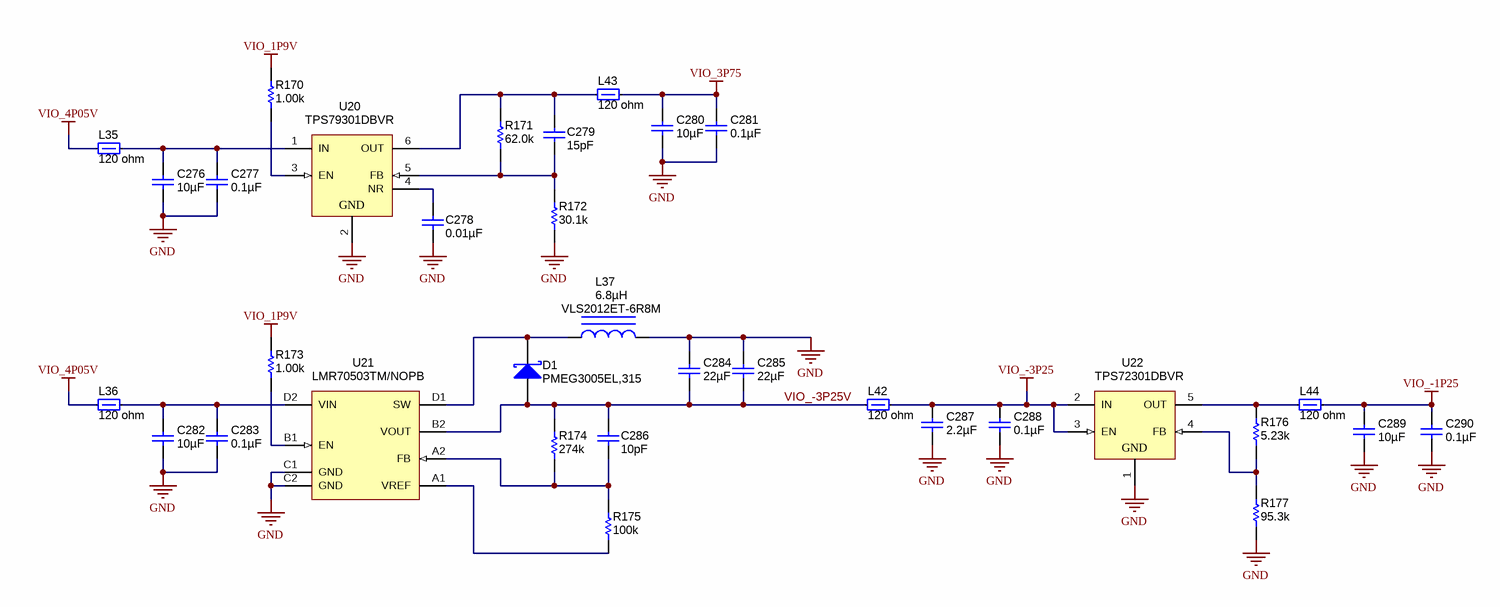
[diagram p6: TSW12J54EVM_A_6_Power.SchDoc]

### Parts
C276  ValueDisplayed: 10µF  [0603L]  (hidden comment: C1608X5R1A106M)
C277  ValueDisplayed: 0.1µF  [0603L]  (hidden comment: 06033C104JAT2A)
C278  ValueDisplayed: 0.01µF  [0603L]  (hidden comment: 06031C103MAT2A)
C279  ValueDisplayed: 15pF  [0603L]  (hidden comment: C0603C150J5GACTU)
C280  ValueDisplayed: 10µF  [0603L]  (hidden comment: C1608X5R1A106M)
C281  ValueDisplayed: 0.1µF  [0603L]  (hidden comment: 06033C104JAT2A)
C282  ValueDisplayed: 10µF  [0603L]  (hidden comment: C1608X5R1A106M)
C283  ValueDisplayed: 0.1µF  [0603L]  (hidden comment: 06033C104JAT2A)
C284  ValueDisplayed: 22µF  [0603L]  (hidden comment: C1608X5R0J226M080AC)
C285  ValueDisplayed: 22µF  [0603L]  (hidden comment: C1608X5R0J226M080AC)
C286  ValueDisplayed: 10pF  [0402L]  (hidden comment: GRM1555C1H100JA01D)
C287  ValueDisplayed: 2.2µF  [0603L]  (hidden comment: GRM188R61A225KE34D)
C288  ValueDisplayed: 0.1µF  [0603L]  (hidden comment: 06033C104JAT2A)
C289  ValueDisplayed: 10µF  [0603L]  (hidden comment: C1608X5R1A106M)
C290  ValueDisplayed: 0.1µF  [0603L]  (hidden comment: 06033C104JAT2A)
D1  PMEG3005EL,315  [SOD882]
L35  value 120 ohm  [0603]  (hidden comment: BLM18SG121TN1D)
L36  value 120 ohm  [0603]  (hidden comment: BLM18SG121TN1D)
L37  VLS2012ET-6R8M  ValueDisplayed: 6.8µH  [VLS2012]
L42  value 120 ohm  [0603]  (hidden comment: BLM18SG121TN1D)
L43  value 120 ohm  [0603]  (hidden comment: BLM18SG121TN1D)
L44  value 120 ohm  [0603]  (hidden comment: BLM18SG121TN1D)
R170  value 1.00k  [0402L]  (hidden comment: CRCW04021K00FKED)
R171  ValueDisplayed: 62.0k  [0603L]  (hidden comment: RC0603FR-0762KL)
R172  ValueDisplayed: 30.1k  [0603L]  (hidden comment: CRCW060330K1FKEA)
R173  value 1.00k  [0402L]  (hidden comment: CRCW04021K00FKED)
R174  ValueDisplayed: 274k  [0402L]  (hidden comment: CRCW0402274KFKED)
R175  ValueDisplayed: 100k  [0402L]  (hidden comment: CRCW0402100KFKED)
R176  ValueDisplayed: 5.23k  [0603L]  (hidden comment: CRCW06035K23FKEA)
R177  ValueDisplayed: 95.3k  [0603L]  (hidden comment: RC0603FR-0795K3L)
U20  TPS79301DBVR  [DBV0006A_N]
U21  LMR70503TM/NOPB  [YFX0008ADAC]
U22  TPS72301DBVR  [DBV0005A_N]

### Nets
GND: C276.2 C277.2 C278.2 C280.2 C281.2 C282.2 C283.2 C284.1 C285.1 C287.2 C288.2 C289.2 C290.2 L37.2 R172.1 R177.1 U20.2(GND) U21.C1(GND) U21.C2(GND) U22.1(GND)
VIO_1P9V: R170.1 R173.1
VIO_3P75: C280.1 C281.1 L43.2
VIO_4P05V: L35.1 L36.1
VIO_-1P25: C289.1 C290.1 L44.2
VIO_-3P25: C287.1 C288.1 L42.2 U22.2(IN) U22.3(EN)
VIO_-3P25V: C284.2 C285.2 C286.1 D1.2(A) L42.1 R174.2 U21.B2(VOUT)
NetC276_1: C276.1 C277.1 L35.2 U20.1(IN)
NetC278_1: C278.1 U20.4(NR)
NetC279_1: C279.1 L43.1 R171.1 U20.6(OUT)
NetC279_2: C279.2 R171.2 R172.2 U20.5(FB)
NetC282_1: C282.1 C283.1 L36.2 U21.D2(VIN)
NetC286_2: C286.2 R174.1 R175.2 U21.A2(FB)
NetD1_1: D1.1(K) L37.1 U21.D1(SW)
NetL44_1: L44.1 R176.2 U22.5(OUT)
NetR170_2: R170.2 U20.3(EN)
NetR173_2: R173.2 U21.B1(EN)
NetR175_1: R175.1 U21.A1(VREF)
NetR176_1: R176.1 R177.2 U22.4(FB)

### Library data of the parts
C276 C280 C282 C289 = C1608X5R1A106M: as C150 on sheet TSW12J54EVM_A_5_Power
C277 C281 C283 C288 C290 = 06033C104JAT2A: as C116 on sheet TSW12J54EVM_A_5_Power
C278 = 06031C103MAT2A: as C128 on sheet TSW12J54EVM_A_5_Power
C279 = C0603C150J5GACTU: CAP, CERM, 15 pF, 50 V, +/- 5%, C0G/NP0, 0603; Manufacturer: Kemet; Polarized: N; CompType: Capacitor; Value: 15pF; U/M: EA; Cap_F: 0.000000000015; Tolerance_%: 5; Value1: Unknown; VDC_V: 50; Value2: 50V; TaMin_C: -55; TaMax_C: 125; Cap_Case: 0603
C284 C285 = C1608X5R0J226M080AC: CAP, CERM, 22 µF, 6.3 V, +/- 20%, X5R, 0603; Manufacturer: TDK; Polarized: N; CompType: Capacitor; Value: 22uF; U/M: EA; Cap_F: 0.000022; Tolerance_%: 20; Value1: Unknown; VDC_V: 6.3; Value2: 6.3V; TaMin_C: -55; TaMax_C: 85; Cap_Case: 0603
C286 = GRM1555C1H100JA01D: CAP, CERM, 10 pF, 50 V, +/- 5%, C0G/NP0, 0402; Manufacturer: MuRata; Polarized: N; CompType: Capacitor; Value: 10pF; U/M: EA; Cap_F: 0.00000000001; Tolerance_%: 5; Value1: Unknown; VDC_V: 50; Value2: 50V; TaMin_C: -55; TaMax_C: 125; Cap_Case: 0402
C287 = GRM188R61A225KE34D: CAP, CERM, 2.2 µF, 10 V, +/- 10%, X5R, 0603; Manufacturer: MuRata; Polarized: N; CompType: Capacitor; Value: 2.2uF; U/M: EA; Cap_F: 0.0000022; Tolerance_%: 10; Value1: Unknown; Value2: 10V; TaMin_C: -55; TaMax_C: 85; Cap_Case: 0603
D1 = PMEG3005EL,315: Diode, Schottky, 30 V, 0.5 A, SOD882; Manufacturer: NXP Semiconductor; U/M: EA; Vf_V: 0.5; Value: 30V; Value1: 0.5A; Value2: 0.5V; Vr_V: 30; TJmax_C: 150
L35 L36 L42-L44 = BLM18SG121TN1D: as L7 on sheet TSW12J54EVM_A_5_Power
L37 = VLS2012ET-6R8M: Inductor, Shielded, Ferrite, 6.8 µH, 0.57 A, 0.498 ohm, SMD; Manufacturer: TDK; Value: 6.8uH; Ind_H: 6.8E-6; Imax_A: 0.57; Irms: 0.69A @ 40C rise; Isat: 0.57A @ 30% inductance drop; DCR_ohm: 0.498; Value2: 0.57A
R170 R173 = CRCW04021K00FKED: RES, 1.00k ohm, 1%, 0.063W, 0402; Manufacturer: Vishay-Dale; CompType: Resistor; Res_ohm: 1000; Value_Code: 1k00; Tolerance_%: 1; Power_W: 0.063; VDC_V: 50; TempCo: 100 ppm/C; EIA_Code: E96; U/M: EA
R171 = RC0603FR-0762KL: RES, 62.0 k, 1%, 0.1 W, 0603; Manufacturer: Yageo America; CompType: Resistor; Value: 62.0k; Res_ohm: 62000; Value_Code: 62k0; Tolerance_%: 1; Power_W: 0.1; Value2: 0.1W; VDC_V: 150; TempCo: 200 ppm/C; U/M: EA
R172 = CRCW060330K1FKEA: RES, 30.1 k, 1%, 0.1 W, 0603; Manufacturer: Vishay-Dale; CompType: Resistor; Value: 30.1k; Res_ohm: 30100; Value_Code: 30k1; Tolerance_%: 1; Power_W: 0.1; Value2: 0.1W; VDC_V: 75; TempCo: 100 ppm/C; EIA_Code: E96; U/M: EA
R174 = CRCW0402274KFKED: RES, 274 k, 1%, 0.063 W, 0402; Manufacturer: Vishay-Dale; CompType: Resistor; Value: 274k; Res_ohm: 274000; Tolerance_%: 1; Power_W: 0.063; Value2: 0.063W; VDC_V: 50; TempCo: 100 ppm/C; EIA_Code: E96; U/M: EA
R175 = CRCW0402100KFKED: RES, 100 k, 1%, 0.063 W, 0402; Manufacturer: Vishay-Dale; CompType: Resistor; Value: 100k; Res_ohm: 100000; Tolerance_%: 1; Power_W: 0.063; Value2: 0.063W; VDC_V: 50; TempCo: 100 ppm/C; EIA_Code: E96; U/M: EA
R176 = CRCW06035K23FKEA: RES, 5.23 k, 1%, 0.1 W, 0603; Manufacturer: Vishay-Dale; CompType: Resistor; Value: 5.23k; Res_ohm: 5230; Value_Code: 5k23; Tolerance_%: 1; Power_W: 0.1; Value2: 0.1W; VDC_V: 75; TempCo: 100 ppm/C; EIA_Code: E96; U/M: EA
R177 = RC0603FR-0795K3L: as R72 on sheet TSW12J54EVM_A_5_Power
U20 = TPS79301DBVR: Single Output High PSRR LDO, 200 mA, Adjustable 1.22 to 5.5 V Output, 2.7 to 5.5 V Input, 6-pin SOT-23 (DBV), -40 to 85 degC, Green (RoHS & no Sb/Br); Manufacturer: Texas Instruments; Alternate Manufacturer: None; Alternate PartNumber: Equivalent; Accuracy(%): 2; Iout(Max)(A): 0.2; Rating: Catalog; SubFamily: Single Channel LDO; Vdo(Typ)(mV): 77; Vin(Max)(V): 5.5; Vin(Min)(V): 2.7; Vout Adj(Min)(V): 1.22
U21 = LMR70503TM/NOPB: SIMPLE SWITCHER Buck-Boost Converter For Negative Output Voltage in uSMD, YFX0008ADAC; Manufacturer: Texas Instruments; SymbolCreator: a0411947; CompType: IC; U/M: EA
U22 = TPS72301DBVR: Single Output LDO, 200 mA, Adjustable -10 to -1.2 V Output, -10 to -2.7 V Input, 5-pin SOT-23 (DBV), -40 to 125 degC, Green (RoHS & no Sb/Br); Manufacturer: Texas Instruments; Alternate Manufacturer: None; Alternate PartNumber: Equivalent; Accuracy(%): 2; Iout(Max)(A): 0.2; Iq(Typ)(mA): 0.13; SubFamily: Single Channel LDO; Vdo(Typ)(mV): 280

## Sheet TSW12J54EVM_A_7_InterfaceControl.SchDoc
size 431 x 279 mm; Date: Not shown in title block; ApprovedBy: Not shown in title block; CheckedBy: Not shown in title block; Author: Not shown in title block; CompanyName: Not shown in title block; Engineer: Not shown in title block; Organization: Not shown in title block; Address1: Not shown in title block; Address2: Not shown in title block; Address3: Not shown in title block; Address4: Not shown in title block; DocumentNumber: 7; Revision: Use project parameter SCH_Rev; SheetNumber: 7; SheetTotal: 8; PageSetup: Record=PageOptions¦CenterHorizontal=True¦CenterVertical=True¦PrintScale=1.00¦XCorrection=1.00¦YCorrection=1.00¦PrintKind=0¦BorderSize=5000000¦LeftOffset=0¦BottomOffset=0¦Orientation=2¦PaperLength=1000¦PaperWidth=1000¦Scale=100¦PaperSource=15¦PrintQuality=600¦MediaType=1¦DitherType=10¦PaperKind=Letter¦PrintScaleMode=1
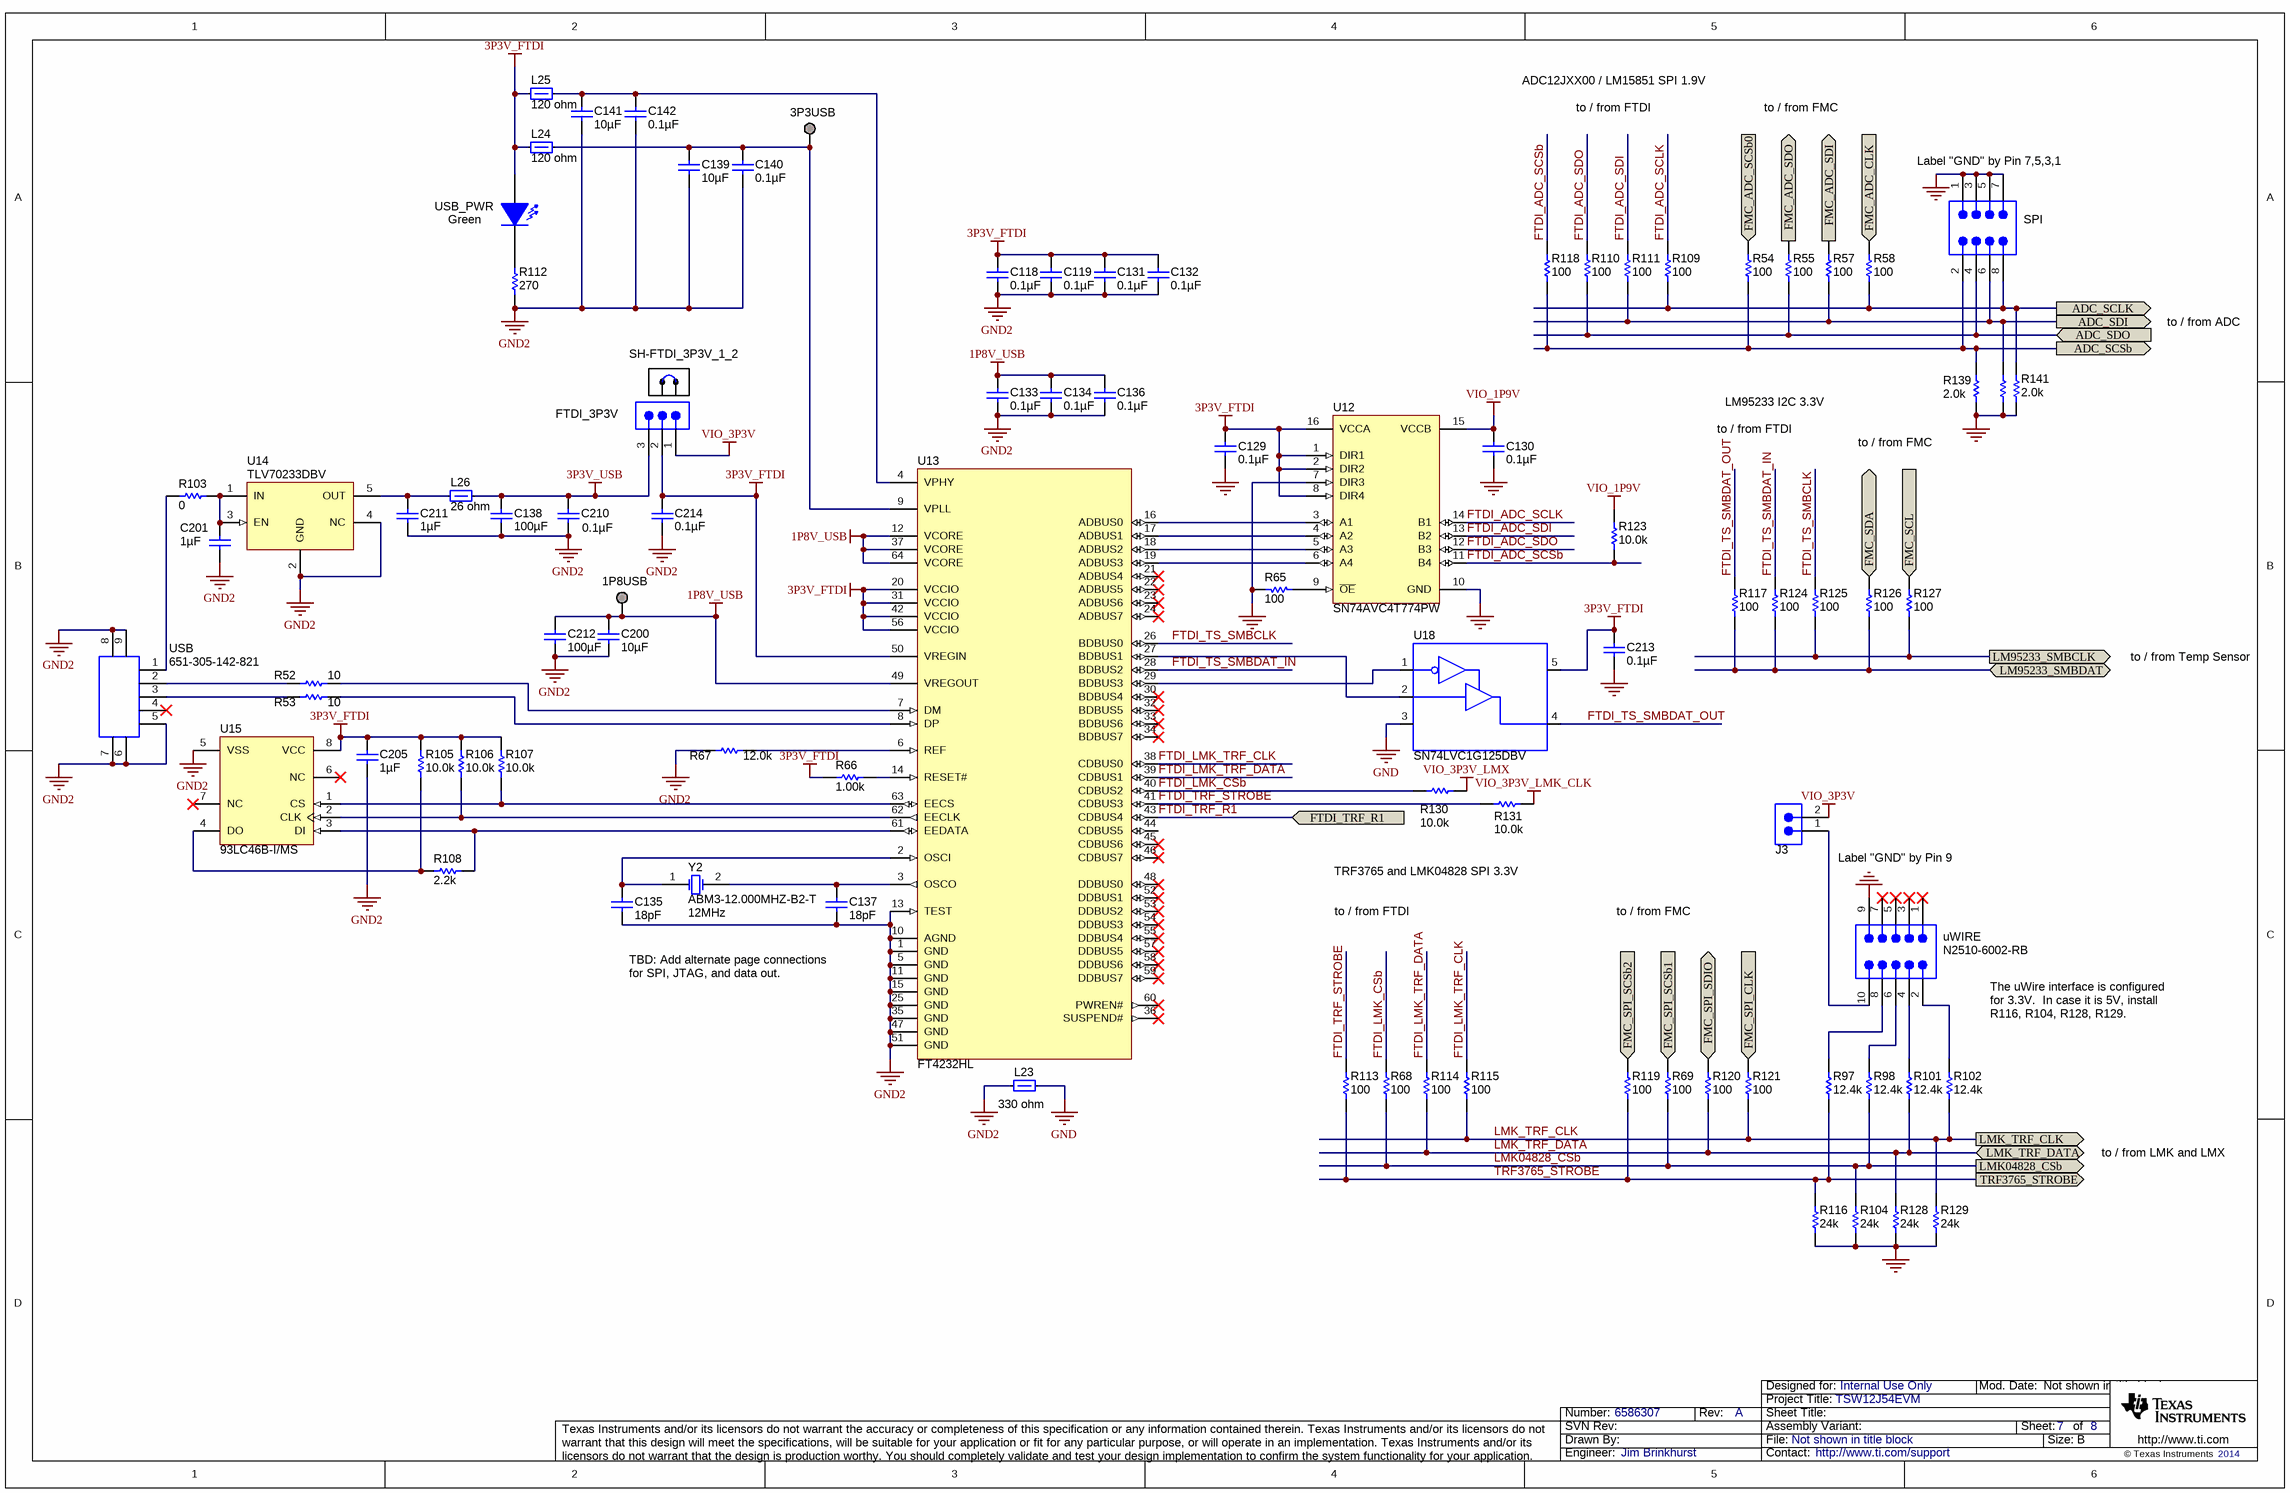
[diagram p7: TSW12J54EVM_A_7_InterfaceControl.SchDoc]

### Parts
1P8USB  TESTPOINT  [TESTPOINT]  (value not drawn)  (no BOM)
3P3USB  TESTPOINT  [TESTPOINT]  (value not drawn)  (no BOM)
C118  ValueDisplayed: 0.1µF  [0201]  (hidden comment: C0603X5R0J104K)
C119  ValueDisplayed: 0.1µF  [0201]  (hidden comment: C0603X5R0J104K)
C129  ValueDisplayed: 0.1µF  [0603L]  (hidden comment: 06033C104JAT2A)
C130  ValueDisplayed: 0.1µF  [0603L]  (hidden comment: 06033C104JAT2A)
C131  ValueDisplayed: 0.1µF  [0201]  (hidden comment: C0603X5R0J104K)
C132  ValueDisplayed: 0.1µF  [0201]  (hidden comment: C0603X5R0J104K)
C133  ValueDisplayed: 0.1µF  [0201]  (hidden comment: C0603X5R0J104K)
C134  ValueDisplayed: 0.1µF  [0201]  (hidden comment: C0603X5R0J104K)
C135  ValueDisplayed: 18pF  [0402L]  (hidden comment: GRM1555C1H180JA01D)
C136  ValueDisplayed: 0.1µF  [0201]  (hidden comment: C0603X5R0J104K)
C137  ValueDisplayed: 18pF  [0402L]  (hidden comment: GRM1555C1H180JA01D)
C138  ValueDisplayed: 100µF  [1206L]  (hidden comment: GRM31CR60J107ME39L)
C139  ValueDisplayed: 10µF  [0603L]  (hidden comment: C1608X5R1A106M)
C140  ValueDisplayed: 0.1µF  [0201]  (hidden comment: C0603X5R0J104K)
C141  ValueDisplayed: 10µF  [0603L]  (hidden comment: C1608X5R1A106M)
C142  ValueDisplayed: 0.1µF  [0201]  (hidden comment: C0603X5R0J104K)
C200  ValueDisplayed: 10µF  [0603L]  (hidden comment: C1608X5R1A106M)
C201  ValueDisplayed: 1µF  [0603L]  (hidden comment: C1608X5R1C105K)
C205  ValueDisplayed: 1µF  [0603L]  (hidden comment: C1608X5R1A105K)
C210  ValueDisplayed: 0.1µF  [0603L]  (hidden comment: 0603YC104JAT2A)
C211  ValueDisplayed: 1µF  [0603L]  (hidden comment: C1608X5R1C105K)
C212  ValueDisplayed: 100µF  [1206]  (hidden comment: GRM31CR60J107ME39L)
C213  ValueDisplayed: 0.1µF  [0603L]  (hidden comment: 06033C104JAT2A)
C214  ValueDisplayed: 0.1µF  [0201]  (hidden comment: C0603X5R0J104K)
FTDI_3P3V  TSW-103-07-G-S  [TSW-103-07-G-S]  (value not drawn)
J3  TSW-102-07-G-S  [TSW-102-07-G-S]  (value not drawn)
L23  value 330 ohm  [0603]  (hidden comment: BLM18SG331TN1D)
L24  value 120 ohm  [0603]  (hidden comment: BLM18SG121TN1D)
L25  value 120 ohm  [0603L]  (hidden comment: BLM18SG121TN1D)
L26  value 26 ohm  [0603]  (hidden comment: BLM18SG260TN1D)
R52  value 10  [0603L]  (hidden comment: CRCW060310R0JNEA)
R53  value 10  [0603L]  (hidden comment: CRCW060310R0JNEA)
R54  value 100  [0603L]  (hidden comment: CRCW0603100RJNEA)
R55  value 100  [0603L]  (hidden comment: CRCW0603100RJNEA)
R57  value 100  [0603L]  (hidden comment: CRCW0603100RJNEA)
R58  value 100  [0603L]  (hidden comment: CRCW0603100RJNEA)
R65  value 100  [0603L]  (hidden comment: CRCW0603100RJNEA)
R66  value 1.00k  [0603L]  (hidden comment: CRCW06031K00FKEA)
R67  value 12.0k  [0603L]  (hidden comment: RC0603FR-0712KL)
R68  value 100  [0603L]  (hidden comment: CRCW0603100RJNEA)
R69  value 100  [0603L]  (hidden comment: CRCW0603100RJNEA)
R97  value 12.4k  [0603L]  (hidden comment: CRCW060312K4FKEA)
R98  value 12.4k  [0603L]  (hidden comment: CRCW060312K4FKEA)
R101  value 12.4k  [0603L]  (hidden comment: CRCW060312K4FKEA)
R102  value 12.4k  [0603L]  (hidden comment: CRCW060312K4FKEA)
R103  value 0  [0603L]  (hidden comment: CRCW06030000Z0EA)
R104  value 24k  [0402L]  (hidden comment: CRCW040224K0JNED)
R105  value 10.0k  [0603L]  (hidden comment: CRCW060310K0FKEA)
R106  value 10.0k  [0603L]  (hidden comment: CRCW060310K0FKEA)
R107  value 10.0k  [0603L]  (hidden comment: CRCW060310K0FKEA)
R108  value 2.2k  [0603L]  (hidden comment: RC0603JR-072K2L)
R109  value 100  [0603L]  (hidden comment: CRCW0603100RJNEA)
R110  value 100  [0603L]  (hidden comment: CRCW0603100RJNEA)
R111  value 100  [0603L]  (hidden comment: CRCW0603100RJNEA)
R112  value 270  [0603L]  (hidden comment: CRCW0603270RJNEA)
R113  value 100  [0603L]  (hidden comment: CRCW0603100RJNEA)
R114  value 100  [0603L]  (hidden comment: CRCW0603100RJNEA)
R115  value 100  [0603L]  (hidden comment: CRCW0603100RJNEA)
R116  value 24k  [0402L]  (hidden comment: CRCW040224K0JNED)
R117  value 100  [0603L]  (hidden comment: CRCW0603100RJNEA)
R118  value 100  [0603L]  (hidden comment: CRCW0603100RJNEA)
R119  value 100  [0603L]  (hidden comment: CRCW0603100RJNEA)
R120  value 100  [0603L]  (hidden comment: CRCW0603100RJNEA)
R121  value 100  [0603L]  (hidden comment: CRCW0603100RJNEA)
R123  value 10.0k  [0603L]  (hidden comment: CRCW060310K0FKEA)
R124  value 100  [0603L]  (hidden comment: CRCW0603100RJNEA)
R125  value 100  [0603L]  (hidden comment: CRCW0603100RJNEA)
R126  value 100  [0603L]  (hidden comment: CRCW0603100RJNEA)
R127  value 100  [0603L]  (hidden comment: CRCW0603100RJNEA)
R128  value 24k  [0402L]  (hidden comment: CRCW040224K0JNED)
R129  value 24k  [0402L]  (hidden comment: CRCW040224K0JNED)
R130  value 10.0k  [0603L]  (hidden comment: CRCW060310K0FKEA)
R131  value 10.0k  [0603L]  (hidden comment: CRCW060310K0FKEA)
R139  value 2.0k  [0603L]  (hidden comment: CRCW06032K00JNEA)
R140  CRCW06032K00JNEA  [0603L]  (value not drawn)
R141  value 2.0k  [0603L]  (hidden comment: CRCW06032K00JNEA)
SH-FTDI_3P3V_1_2  SNT-100-BK-G  [SNT-100-BK-G]  (value not drawn)
SPI  TSW-104-07-G-D  [TSW-104-07-G-D]  (value not drawn)
U12  SN74AVC4T774PW  [PW0016A_L]
U13  FT4232HL  [LQFP64_N]
U14  TLV70233DBV  [DBV0005A_N]
U15  93LC46B-I/MS  [MSOP-MS8_N]
U18  SN74LVC1G125DBV  [SOP-5_.95MM_(DBV)]
USB  651-305-142-821  [CONN_USB-MINI-AB-651-305-142-821]
USB_PWR  value Green  [LED_LTST-C190]  (hidden comment: LTST-C190GKT)
uWIRE  N2510-6002-RB  [CONN_2510-6002]
Y2  ABM3-12.000MHZ-B2-T  Frequency: 12MHz  [XTAL_ABM3]

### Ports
ADC_SCLK (out), ADC_SCSb (out), ADC_SDI (out), ADC_SDO (in), FMC_ADC_CLK (in), FMC_ADC_SCSb0 (in), FMC_ADC_SDI (out), FMC_ADC_SDO (in), FMC_SCL (out), FMC_SDA (bidir), FMC_SPI_CLK (in), FMC_SPI_SCSb1 (in), FMC_SPI_SCSb2 (in), FMC_SPI_SDIO (bidir), FTDI_TRF_R1, LM95233_SMBCLK (out), LM95233_SMBDAT (bidir), LMK04828_CSb (out), LMK_TRF_CLK, LMK_TRF_DATA (bidir), TRF3765_STROBE (out)

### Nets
1P8V_USB: 1P8USB.1 C133.1 C134.1 C136.1 C200.1 C212.2 U13.12(VCORE) U13.37(VCORE) U13.49(VREGOUT) U13.64(VCORE)
3P3V_FTDI: C118.1 C119.1 C129.1 C131.1 C132.1 C205.1 C213.1 C214.1 FTDI_3P3V.2 L24.1 L25.1 R66.2 R105.2 R106.2 R107.2 U12.1(DIR1) U12.2(DIR2) U12.8(DIR4) U12.16(VCCA) U13.20(VCCIO) U13.31(VCCIO) U13.42(VCCIO) U13.50(VREGIN) U13.56(VCCIO) U15.8(VCC) U18.5(VCC) USB_PWR.1(A)
3P3V_USB: C138.1 C210.1 FTDI_3P3V.3 L26.2
GND: C129.2 C130.2 C213.2 L23.2 R65.1 R104.1 R116.1 R128.1 R129.1 R139.1 R140.1 R141.1 SPI.1 SPI.3 SPI.5 SPI.7 U12.7(DIR3) U12.10(GND) U18.3(GND) uWIRE.9
GND2: C118.2 C119.2 C131.2 C132.2 C133.2 C134.2 C135.2 C136.2 C137.2 C138.2 C139.2 C140.2 C141.2 C142.2 C200.2 C201.2 C205.2 C210.2 C211.2 C212.1 C214.2 L23.1 R67.1 R112.1 U13.1(GND) U13.5(GND) U13.10(AGND) U13.11(GND) U13.13(TEST) U13.15(GND) U13.25(GND) U13.35(GND) U13.47(GND) U13.51(GND) U14.2(GND) U14.4(NC) U15.5(VSS) USB.5 USB.6 USB.7 USB.8 USB.9
VIO_1P9V: C130.1 R123.2 U12.15(VCCB)
VIO_3P3V: FTDI_3P3V.1 J3.2
VIO_3P3V_LMK_CLK: R131.1
VIO_3P3V_LMX: R130.1
FTDI_ADC_SCLK: R109.2 U12.14(B1)
FTDI_ADC_SCSb: R118.2 R123.1 U12.11(B4)
FTDI_ADC_SDI: R111.2 U12.13(B2)
FTDI_ADC_SDO: R110.2 U12.12(B3)
FTDI_LMK_CSb: R68.2 R130.2 U13.40(CDBUS2)
FTDI_LMK_TRF_CLK: R115.2 U13.38(CDBUS0)
FTDI_LMK_TRF_DATA: R114.2 U13.39(CDBUS1)
FTDI_TRF_R1: U13.43(CDBUS4) ; port FTDI_TRF_R1
FTDI_TRF_STROBE: R113.2 R131.2 U13.41(CDBUS3)
FTDI_TS_SMBCLK: R125.2 U13.26(BDBUS0)
FTDI_TS_SMBDAT_IN: R124.2 U13.28(BDBUS2)
FTDI_TS_SMBDAT_OUT: R117.2 U18.4(Y)
LMK04828_CSb: R68.1 R69.1 R98.1 R104.2 ; port LMK04828_CSb
LMK_TRF_CLK: R102.1 R115.1 R121.1 R129.2 ; port LMK_TRF_CLK
LMK_TRF_DATA: R101.1 R114.1 R120.1 R128.2 ; port LMK_TRF_DATA
TRF3765_STROBE: R97.1 R113.1 R116.2 R119.1 ; port TRF3765_STROBE
Net3P3USB_1: 3P3USB.1 C139.1 C140.1 L24.2 U13.9(VPLL)
NetC135_1: C135.1 U13.2(OSCI) Y2.1(OSC1)
NetC137_1: C137.1 U13.3(OSCO) Y2.2(OSC2)
NetC141_1: C141.1 C142.1 L25.2 U13.4(VPHY)
NetC201_1: C201.1 R103.2 U14.1(IN) U14.3(EN)
NetC211_1: C211.1 L26.1 U14.5(OUT)
NetFMC_RX1_C30: R127.2 ; port FMC_SCL
NetFMC_RX1_C31: R126.2 ; port FMC_SDA
NetFMC_RX1_G30: R121.2 ; port FMC_SPI_CLK
NetFMC_RX1_G33: R69.2 ; port FMC_SPI_SCSb1
NetFMC_RX1_G34: R119.2 ; port FMC_SPI_SCSb2
NetFMC_RX1_G36: R57.2 ; port FMC_ADC_SDI
NetFMC_RX1_G37: R55.2 ; port FMC_ADC_SDO
NetFMC_RX1_H34: R120.2 ; port FMC_SPI_SDIO
NetFMC_RX1_H37: R58.2 ; port FMC_ADC_CLK
NetFMC_RX1_H38: R54.2 ; port FMC_ADC_SCSb0
NetJ3_1: J3.1 uWIRE.10
NetR31_1: R117.1 R124.1 R126.1 ; port LM95233_SMBDAT
NetR32_1: R125.1 R127.1 ; port LM95233_SMBCLK
NetR52_1: R52.1 USB.2
NetR52_2: R52.2 U13.7(DM)
NetR53_1: R53.1 USB.3
NetR53_2: R53.2 U13.8(DP)
NetR54_1: R54.1 R118.1 R139.2 SPI.2 ; port ADC_SCSb
NetR55_1: R55.1 R110.1 SPI.4 ; port ADC_SDO
NetR57_1: R57.1 R111.1 R140.2 SPI.6 ; port ADC_SDI
NetR58_1: R58.1 R109.1 R141.2 SPI.8 ; port ADC_SCLK
NetR65_2: R65.2 U12.9(~{OE})
NetR66_1: R66.1 U13.14(RESET#)
NetR67_2: R67.2 U13.6(REF)
NetR97_2: R97.2 uWIRE.8
NetR98_2: R98.2 uWIRE.6
NetR101_2: R101.2 uWIRE.4
NetR102_2: R102.2 uWIRE.2
NetR103_1: R103.1 USB.1
NetR105_1: R105.1 R108.2 U15.4(DO)
NetR106_1: R106.1 U13.62(EECLK) U15.2(CLK)
NetR107_1: R107.1 U13.63(EECS) U15.1(CS)
NetR108_1: R108.1 U13.61(EEDATA) U15.3(DI)
NetR112_2: R112.2 USB_PWR.2(K)
NetU12_3: U12.3(A1) U13.16(ADBUS0)
NetU12_4: U12.4(A2) U13.17(ADBUS1)
NetU12_5: U12.5(A3) U13.18(ADBUS2)
NetU12_6: U12.6(A4) U13.19(ADBUS3)
NetU13_27: U13.27(BDBUS1) U18.2(A)
NetU13_29: U13.29(BDBUS3) U18.1(~OE)

Not connected (* = marked no-connect by the designer): U13 21(ADBUS4)* 22(ADBUS5)* 23(ADBUS6)* 24(ADBUS7)* 30(BDBUS4)* 32(BDBUS5)* 33(BDBUS6)* 34(BDBUS7)* 36(SUSPEND#)* 44(CDBUS5) 45(CDBUS6)* 46(CDBUS7)* 48(DDBUS0)* 52(DDBUS1)* 53(DDBUS2)* 54(DDBUS3)* 55(DDBUS4)* 57(DDBUS5)* 58(DDBUS6)* 59(DDBUS7)* 60(PWREN#)*; U15 6(NC)* 7(NC)*; USB 4*; uWIRE 1* 3* 5* 7*

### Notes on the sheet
- ADC12JXX00 / LM15851 SPI 1.9V
- to / from FTDI
- to / from FMC
- (near SPI) Label "GND" by Pin 7,5,3,1
- to / from ADC
- LM95233 I2C 3.3V
- to / from Temp Sensor
- TRF3765 and LMK04828 SPI 3.3V
- Label "GND" by Pin 9
- TBD: Add alternate page connections for SPI, JTAG, and data out.
- The uWire interface is configured for 3.3V.  In case it is 5V, install R116, R104, R128, R129.
- to / from LMK and LMX

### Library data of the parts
1P8USB 3P3USB = TESTPOINT: TEST POINT.  No entry in BOM.
C118 C119 C131-C134 C136 C140 C142 C214 = Capacitor: CAP, CERM, 0.1uF, 6.3V, X5R, 10%, 0201; Manufacturer: TDK; Polarized: N; U/M: EA
C129 C130 C213 = 06033C104JAT2A: as C116 on sheet TSW12J54EVM_A_5_Power
C135 C137 = GRM1555C1H180JA01D: CAP, CERM, 18pF, 50V, +/-5%, C0G/NP0, 0402; Manufacturer: MuRata; Polarized: N; CompType: Capacitor; U/M: EA; Cap_F: 0.000000000018; Tolerance_%: 5; Value1: Unknown; VDC_V: 50; TaMin_C: -55; TaMax_C: 125; Cap_Case: 0402
C138 = GRM31CR60J107ME39L: CAP, CERM, 100uF, 6.3V, +/-20%, X5R, 1206; Manufacturer: MuRata; Polarized: N; CompType: Capacitor; U/M: EA; Cap_F: 0.0001; Tolerance_%: 20; ESR_Ohm: 0.003; Value1: 0.003 ohm; VDC_V: 6.3; TaMin_C: -55; TaMax_C: 85; Cap_Case: 1206
C139 C141 C200 = C1608X5R1A106M: as C150 on sheet TSW12J54EVM_A_5_Power
C201 C211 = C1608X5R1C105K: as C155 on sheet TSW12J54EVM_A_5_Power
C205 = C1608X5R1A105K: CAP, CERM, 1uF, 10V, +/-10%, X5R, 0603; Manufacturer: TDK; Polarized: N; CompType: Capacitor; U/M: EA; Cap_F: 0.000001; Tolerance_%: 10; ESR_Ohm: 0.0057; Value1: 0.0057 ohm; TaMin_C: -55; TaMax_C: 85; Cap_Case: 0603
C210 = 0603YC104JAT2A: CAP, CERM, 0.1uF, 16V, +/-5%, X7R, 0603; Manufacturer: AVX; Polarized: N; CompType: Capacitor; U/M: EA; Cap_F: 0.0000001; Tolerance_%: 5; ESR_Ohm: 0.039; Value1: 0.039 ohm; VDC_V: 16; TaMin_C: -55; TaMax_C: 125; Cap_Case: 0603
C212 = GRM31CR60J107ME39L: CAP, CERM, 100uF, 6.3V, +/-20%, X5R, 1206; Manufacturer: MuRata; Polarized: N; CompType: Capacitor; U/M: EA; Cap_F: 0.0001; Tolerance_%: 20; ESR_Ohm: 0.003; Value1: 0.003 ohm; VDC_V: 6.3; TaMin_C: -55; TaMax_C: 85
FTDI_3P3V = TSW-103-07-G-S: Header, TH, 100mil, 3x1, Gold plated, 230 mil above insulator; Manufacturer: Samtec, Inc.; Alternate Manufacturer: Any; Alternate PartNumber: Equivalent; U/M: EA
J3 = TSW-102-07-G-S: as 1V2ADC_INT on sheet TSW12J54EVM_A_5_Power
L23 = BLM18SG331TN1D: 1.5A Ferrite Bead, 330 ohm @ 100MHz, SMD; Manufacturer: MuRata; Imax_A: 1.5; DCR_ohm: 0.07; Value1: 0.07 ohm; ZTyp@100MHz_Ohm: 330; U/M: EA
L24 L25 = BLM18SG121TN1D: as L7 on sheet TSW12J54EVM_A_5_Power
L26 = BLM18SG260TN1D: as L6 on sheet TSW12J54EVM_A_5_Power
R52 R53 = CRCW060310R0JNEA: RES, 10 ohm, 5%, 0.1W, 0603; Manufacturer: Vishay-Dale; CompType: Resistor; Value_Code: 10R0; Tolerance_%: 5; Power_W: 0.1; VDC_V: 75; TempCo: 200 ppm/C; EIA_Code: E24; U/M: EA
R54 R55 R57 R58 R65 R68 R69 R109-R111 R113-R115 R117-R121 R124-R127 = CRCW0603100RJNEA: RES, 100 ohm, 5%, 0.1W, 0603; Manufacturer: Vishay-Dale; CompType: Resistor; Value_Code: 100R; Tolerance_%: 5; Power_W: 0.1; VDC_V: 75; TempCo: 200 ppm/C; EIA_Code: E24; U/M: EA
R66 = CRCW06031K00FKEA: RES, 1.00k ohm, 1%, 0.1W, 0603; Manufacturer: Vishay-Dale; CompType: Resistor; Tolerance_%: 1; VDC_V: 75; Power_W: 0.1; Res_ohm: 1000; TempCo_ppm/C: 100; Value_Code: 1k00; EIA_Code: E96; U/M: EA
R67 = RC0603FR-0712KL: RES, 12.0k ohm, 1%, 0.1W, 0603; Manufacturer: Yageo America; CompType: Resistor; Res_ohm: 12000; Value_Code: 12k0; Tolerance_%: 1; Power_W: 0.1; VDC_V: 150; TempCo: 200 ppm/C; U/M: EA
R97 R98 R101 R102 = CRCW060312K4FKEA: RES, 12.4k ohm, 1%, 0.1W, 0603; Manufacturer: Vishay-Dale; CompType: Resistor; Res_ohm: 12400; Value_Code: 12k4; Tolerance_%: 1; Power_W: 0.1; VDC_V: 75; TempCo: 100 ppm/C; EIA_Code: E96; U/M: EA
R103 = CRCW06030000Z0EA: RES, 0 ohm, 5%, 0.1W, 0603; Manufacturer: Vishay-Dale; CompType: Resistor; Value_Code: 0000; Tolerance_%: 5; Power_W: 0.1; VDC_V: 75; TempCo: 200 ppm/C; EIA_Code: E24; U/M: EA
R104 R116 R128 R129 = CRCW040224K0JNED: RES, 24k ohm, 5%, 0.063W, 0402; Manufacturer: Vishay-Dale; CompType: Resistor; Res_ohm: 24000; Value_Code: 24k0; Tolerance_%: 5; Power_W: 0.063; VDC_V: 50; TempCo: 200 ppm/C; EIA_Code: E24; U/M: EA
R105-R107 R123 R130 R131 = CRCW060310K0FKEA: RES, 10.0k ohm, 1%, 0.1W, 0603; Manufacturer: Vishay-Dale; CompType: Resistor; Res_ohm: 10000; Value_Code: 10k0; Tolerance_%: 1; Power_W: 0.1; VDC_V: 75; TempCo: 100 ppm/C; EIA_Code: E96; U/M: EA
R108 = RC0603JR-072K2L: RES, 2.2k ohm, 5%, 0.1W, 0603; Manufacturer: Yageo America; CompType: Resistor; Res_ohm: 2200; Value_Code: 2k20; Tolerance_%: 5; Power_W: 0.1; VDC_V: 50; TempCo: 100 ppm/C; EIA_Code: E24; U/M: EA
R112 = CRCW0603270RJNEA: RES, 270 ohm, 5%, 0.1W, 0603; Manufacturer: Vishay-Dale; Alternate Manufacturer: Any; Alternate PartNumber: Equivalent; CompType: Resistor; Value_Code: 270R; Tolerance_%: 5; Power_W: 0.1; VDC_V: 75; TempCo: 200 ppm/C; EIA_Code: E24; U/M: EA
R139-R141 = CRCW06032K00JNEA: RES, 2.0k ohm, 5%, 0.1W, 0603; Manufacturer: Vishay-Dale; CompType: Resistor; Res_ohm: 2000; Value_Code: 2k00; Tolerance_%: 5; Power_W: 0.1; VDC_V: 75; TempCo: 200 ppm/C; EIA_Code: E24; U/M: EA
SH-FTDI_3P3V_1_2 = SNT-100-BK-G: as SH-1V2ADC_INT_1_2 on sheet TSW12J54EVM_A_5_Power
SPI = TSW-104-07-G-D: Header, TH, 100mil, 4x2, Gold plated, 230 mil above insulator; Manufacturer: Samtec, Inc.; U/M: EA
U12 = SN74AVC4T774PW: 4-BIT DUAL-SUPPLY BUS TRANSCEIVER WITH CONFIGURABLE VOLTAGE TRANSLATION AND 3-STATE OUTPUTS, PW0016A; Alternate Manufacturer: None; Manufacturer: Texas Instruments; SymbolCreator: a0411947; CompType: IC; U/M: EA
U13 = FT4232HL: Quad High Speed USB to Multipurpose UART/MPSSE IC; Manufacturer: FTDI; SymbolCreator: a0411947
U14 = TLV70233DBV: 300-mA, Low-IQ, Low-Dropout Regulator, DBV0005A; Alternate Manufacturer: None; Manufacturer: Texas Instruments; SymbolCreator: a0411947; CompType: IC; U/M: EA
U15 = 93LC46B-I/MS: 1K, 64x16-bit, 2.5V Microwire Serial EEPROM, 8-Pin MSOP, Industrial Temperature; Manufacturer: Microchip Technology
U18 = SN74LVC1G125DBV: IC, Single Bus Buffer Gate With 3-States Output; Manufacturer: TI; Alternate Manufacturer: None; Area: 24,883
USB = 651-305-142-821: MINI USB 2.0 SMT TYPE AB 5 CONTACTS R/A, SMD; Manufacturer: Wurth Elektronik eiSos; SymbolCreator: a0799628; CompType: Connector; U/M: EA
USB_PWR = LTST-C190GKT: as 12V on sheet TSW12J54EVM_A_5_Power
uWIRE = N2510-6002-RB: Connector, 100mil Shrouded, 5x2, High-Temperature, Gold, TH; Manufacturer: 3M; SymbolCreator: a0412235; U/M: EA
Y2 = ABM3-12.000MHZ-B2-T: Crystal, 12Mhz, 18pF, SMD; Manufacturer: Abracon Corportation; SymbolCreator: a0412235; U/M: EA; TaMin_C: -20; TaMax_C: 70; Frequency Stability: ±50ppm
